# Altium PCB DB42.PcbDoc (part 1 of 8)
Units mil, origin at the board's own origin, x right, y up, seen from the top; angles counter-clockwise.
Board outline 3236.22 x 4456.69 mil, 8 copper layers (Top Layer, MidLayer1, MidLayer2, GND-Layer5, MidLayer3, VCC, MidLayer4, Bottom Layer), stack 62.194 mil thick; 214 components, 470 nets, 1802 pads, 1663 vias.
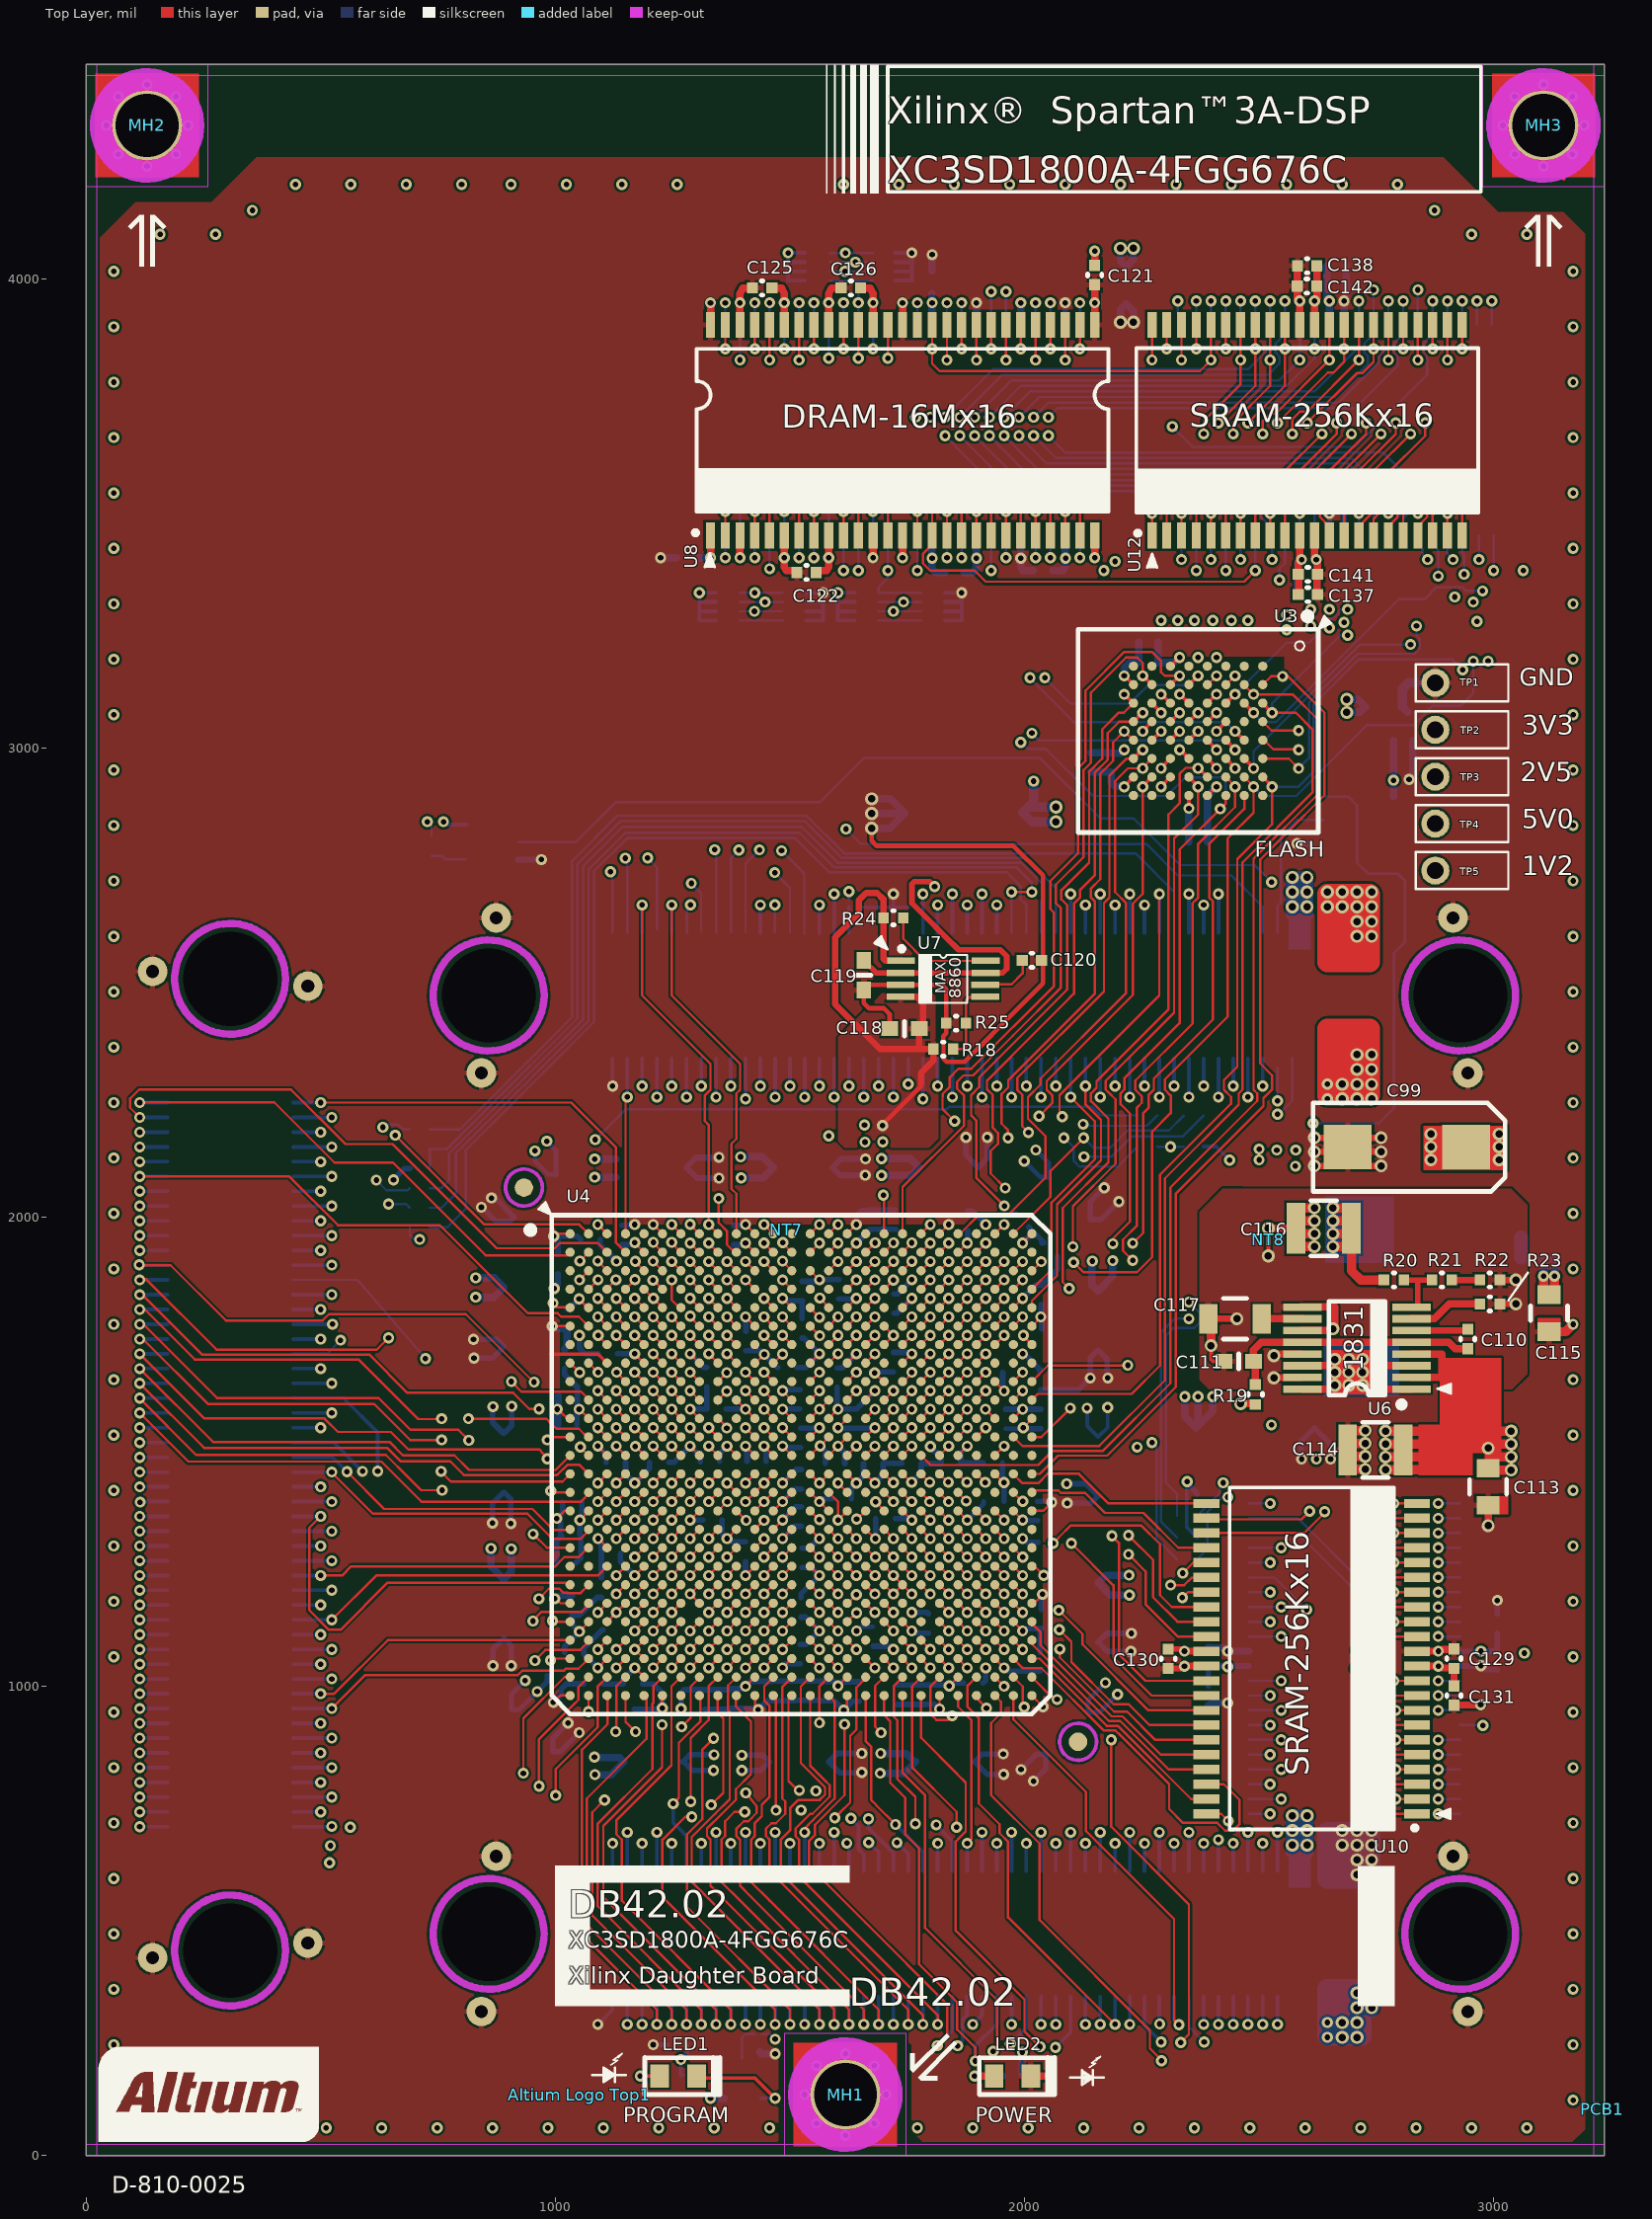
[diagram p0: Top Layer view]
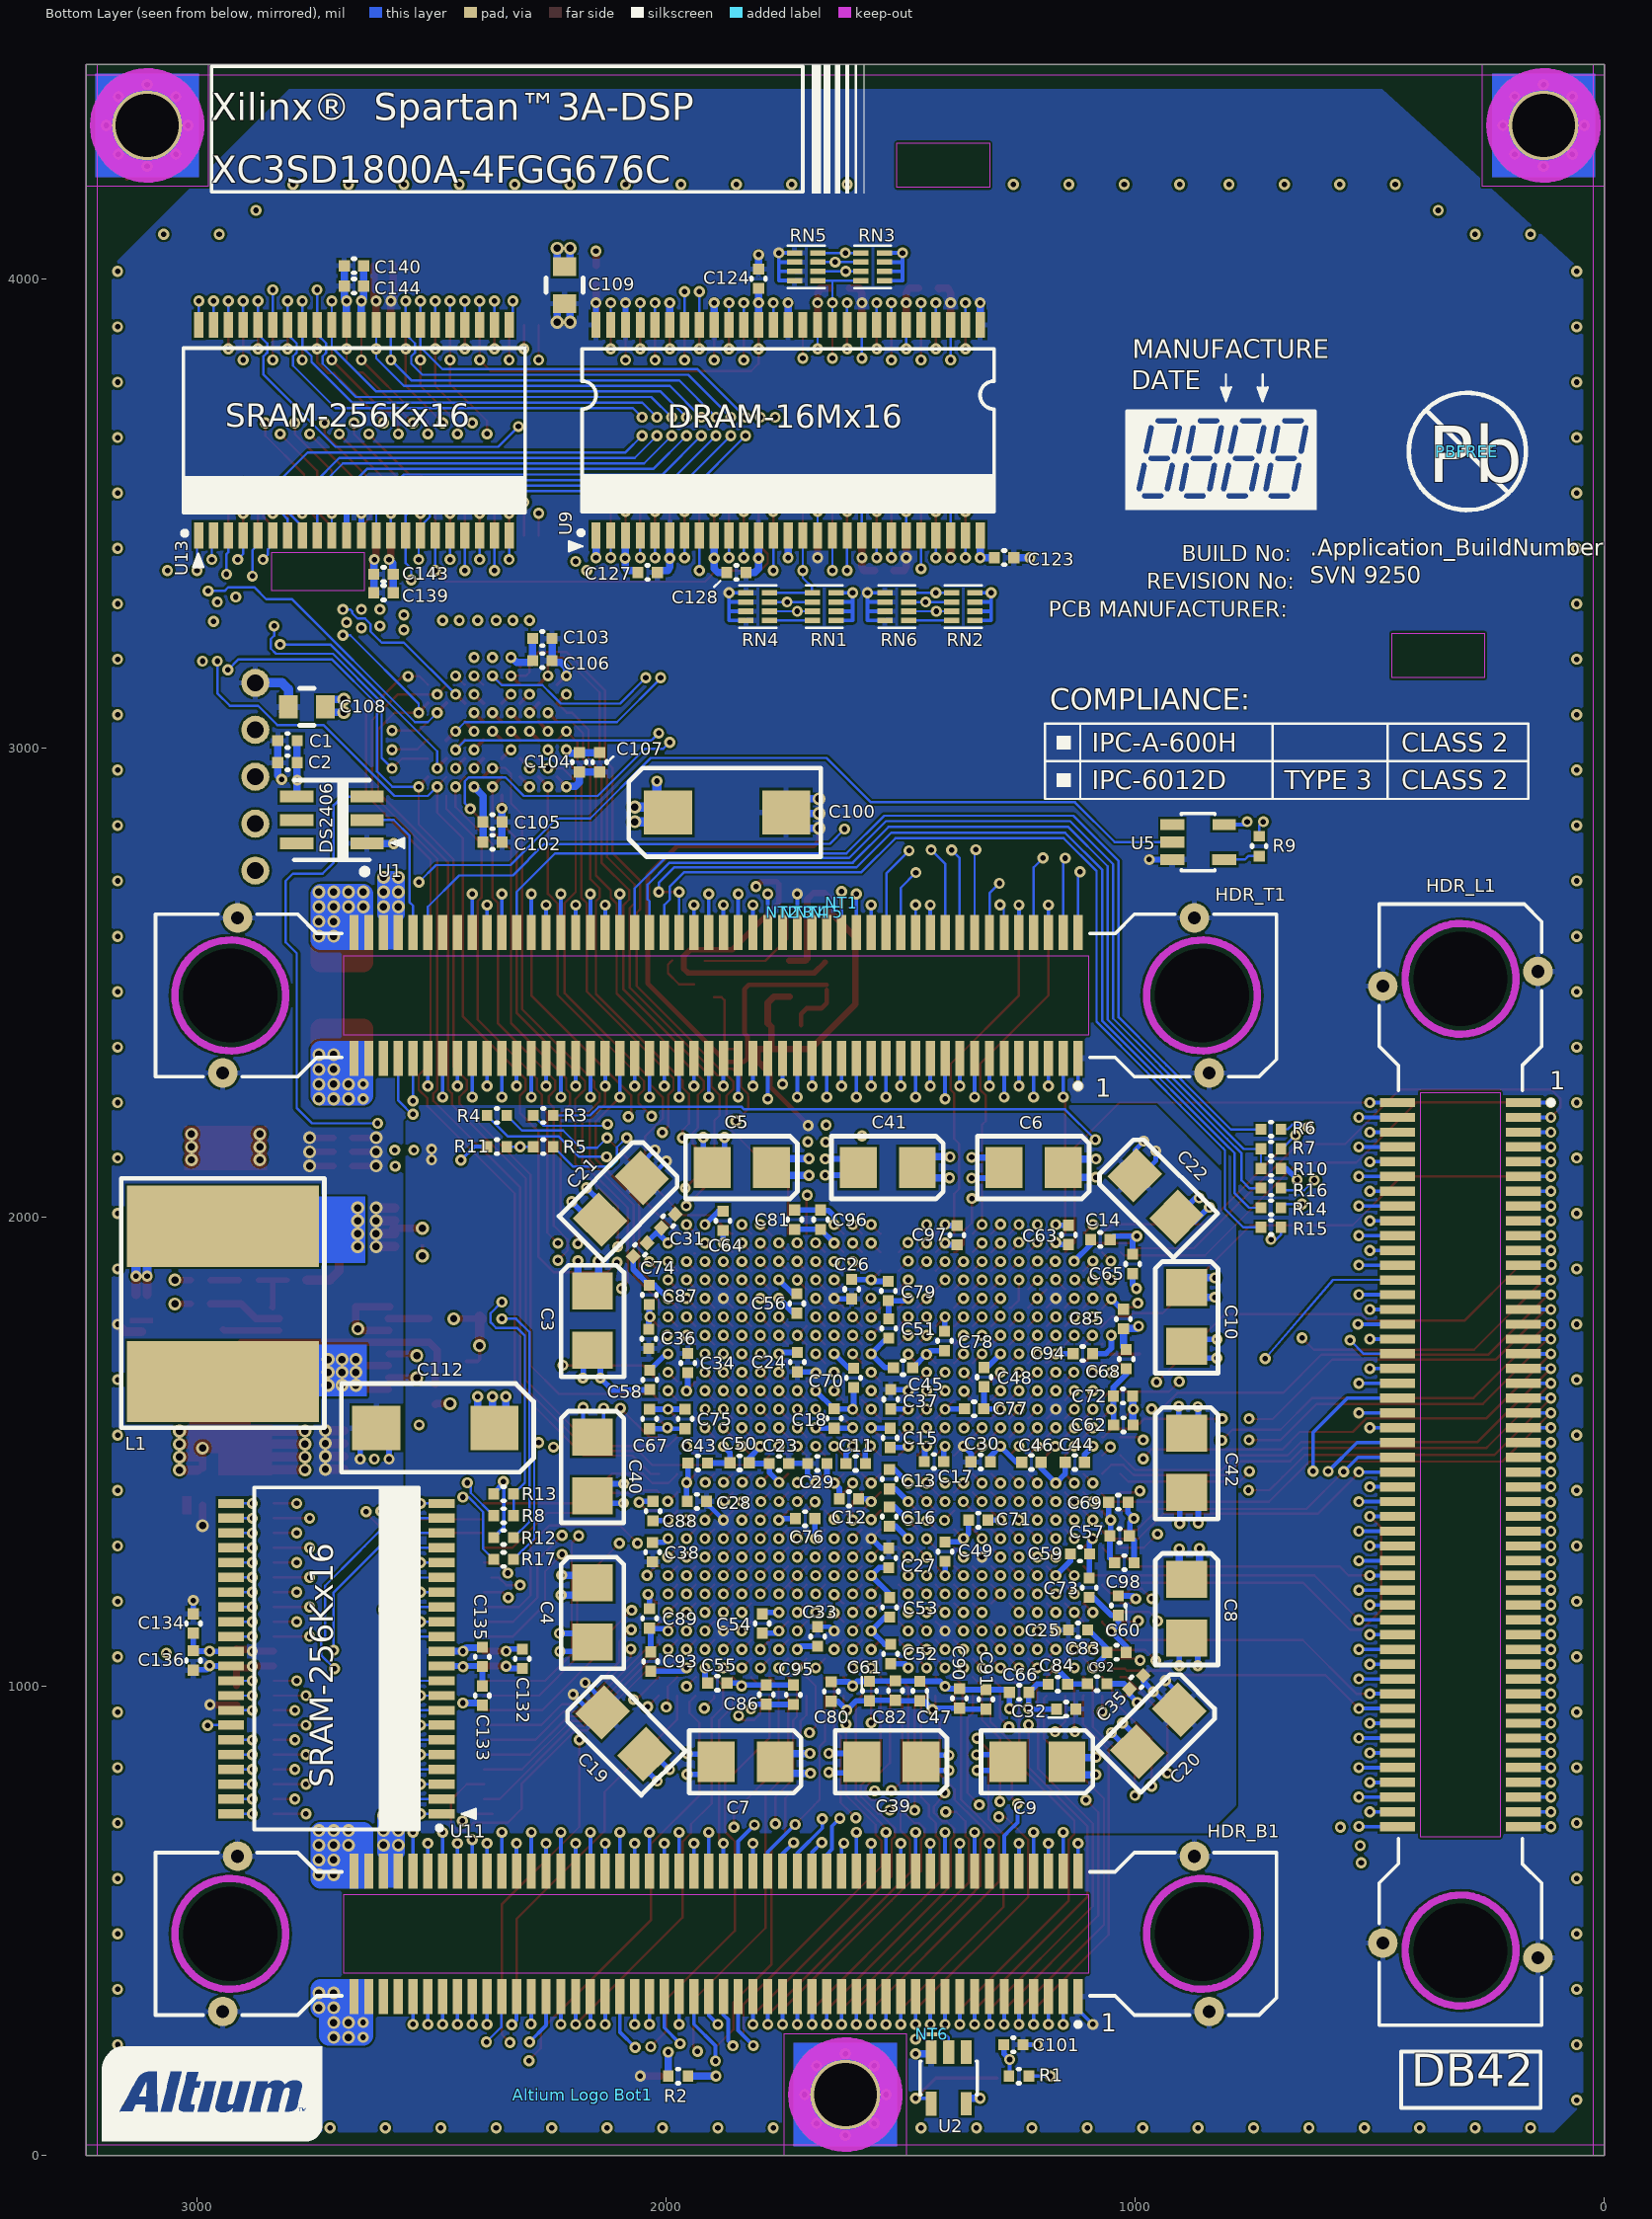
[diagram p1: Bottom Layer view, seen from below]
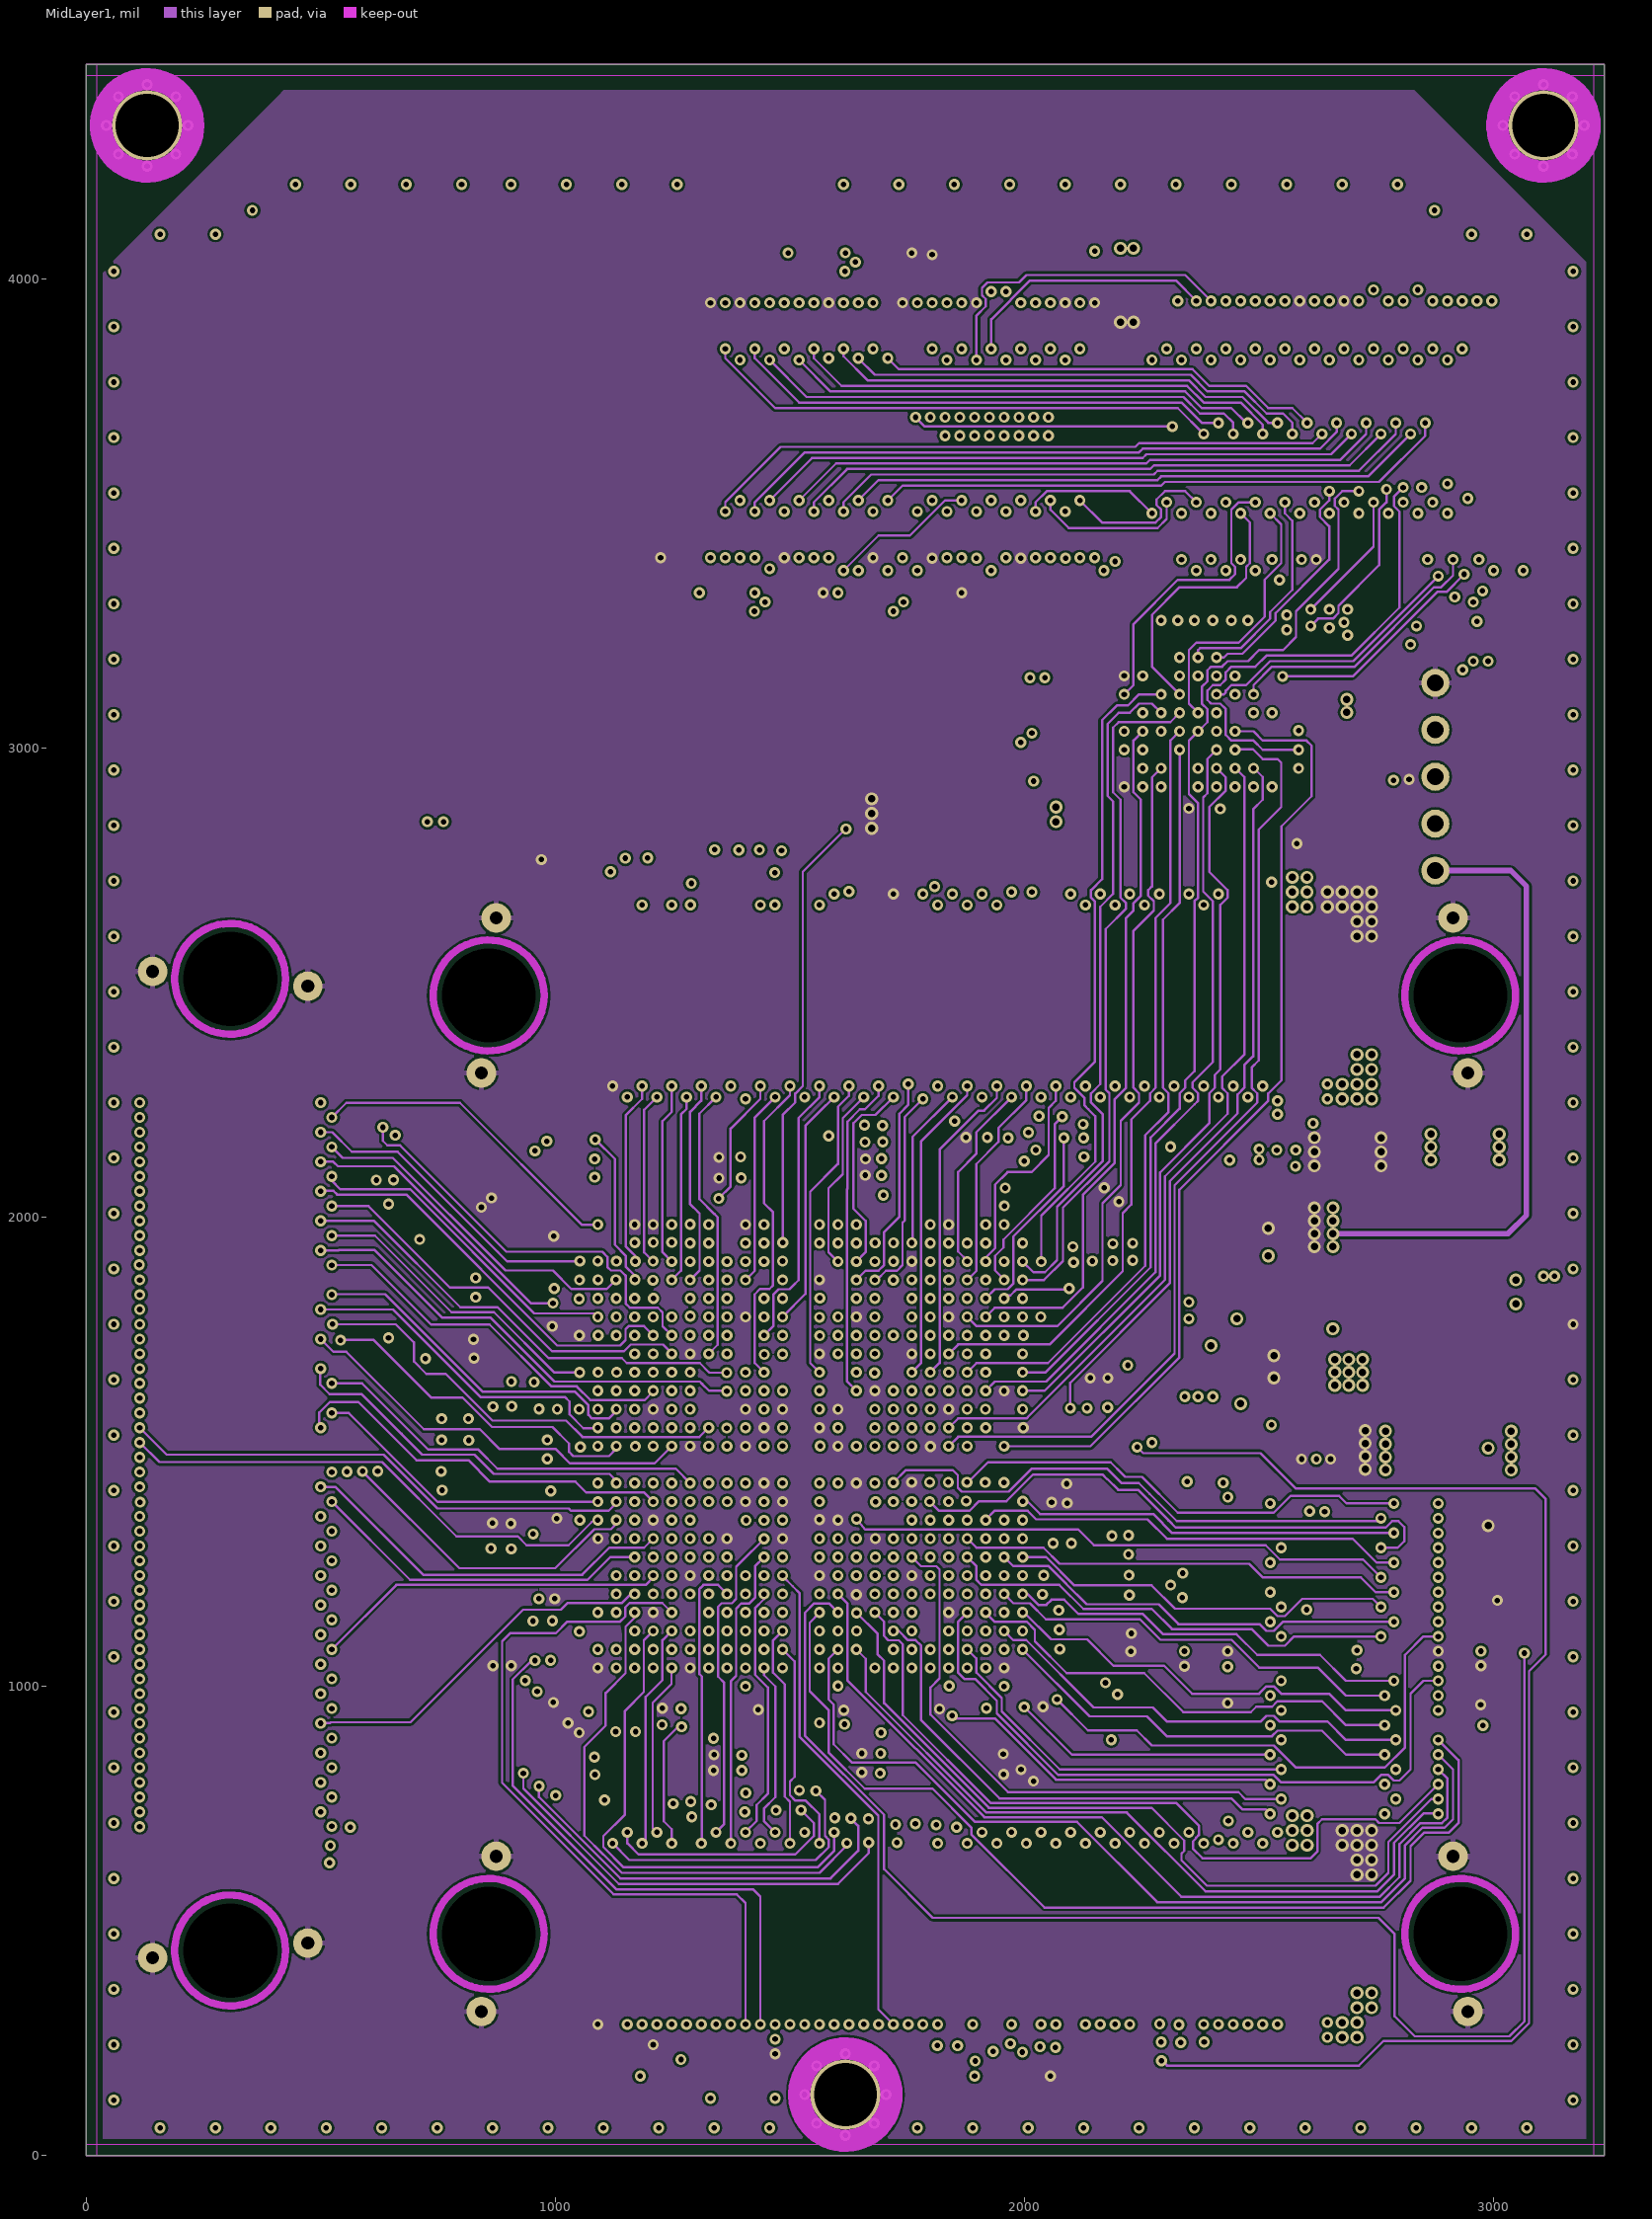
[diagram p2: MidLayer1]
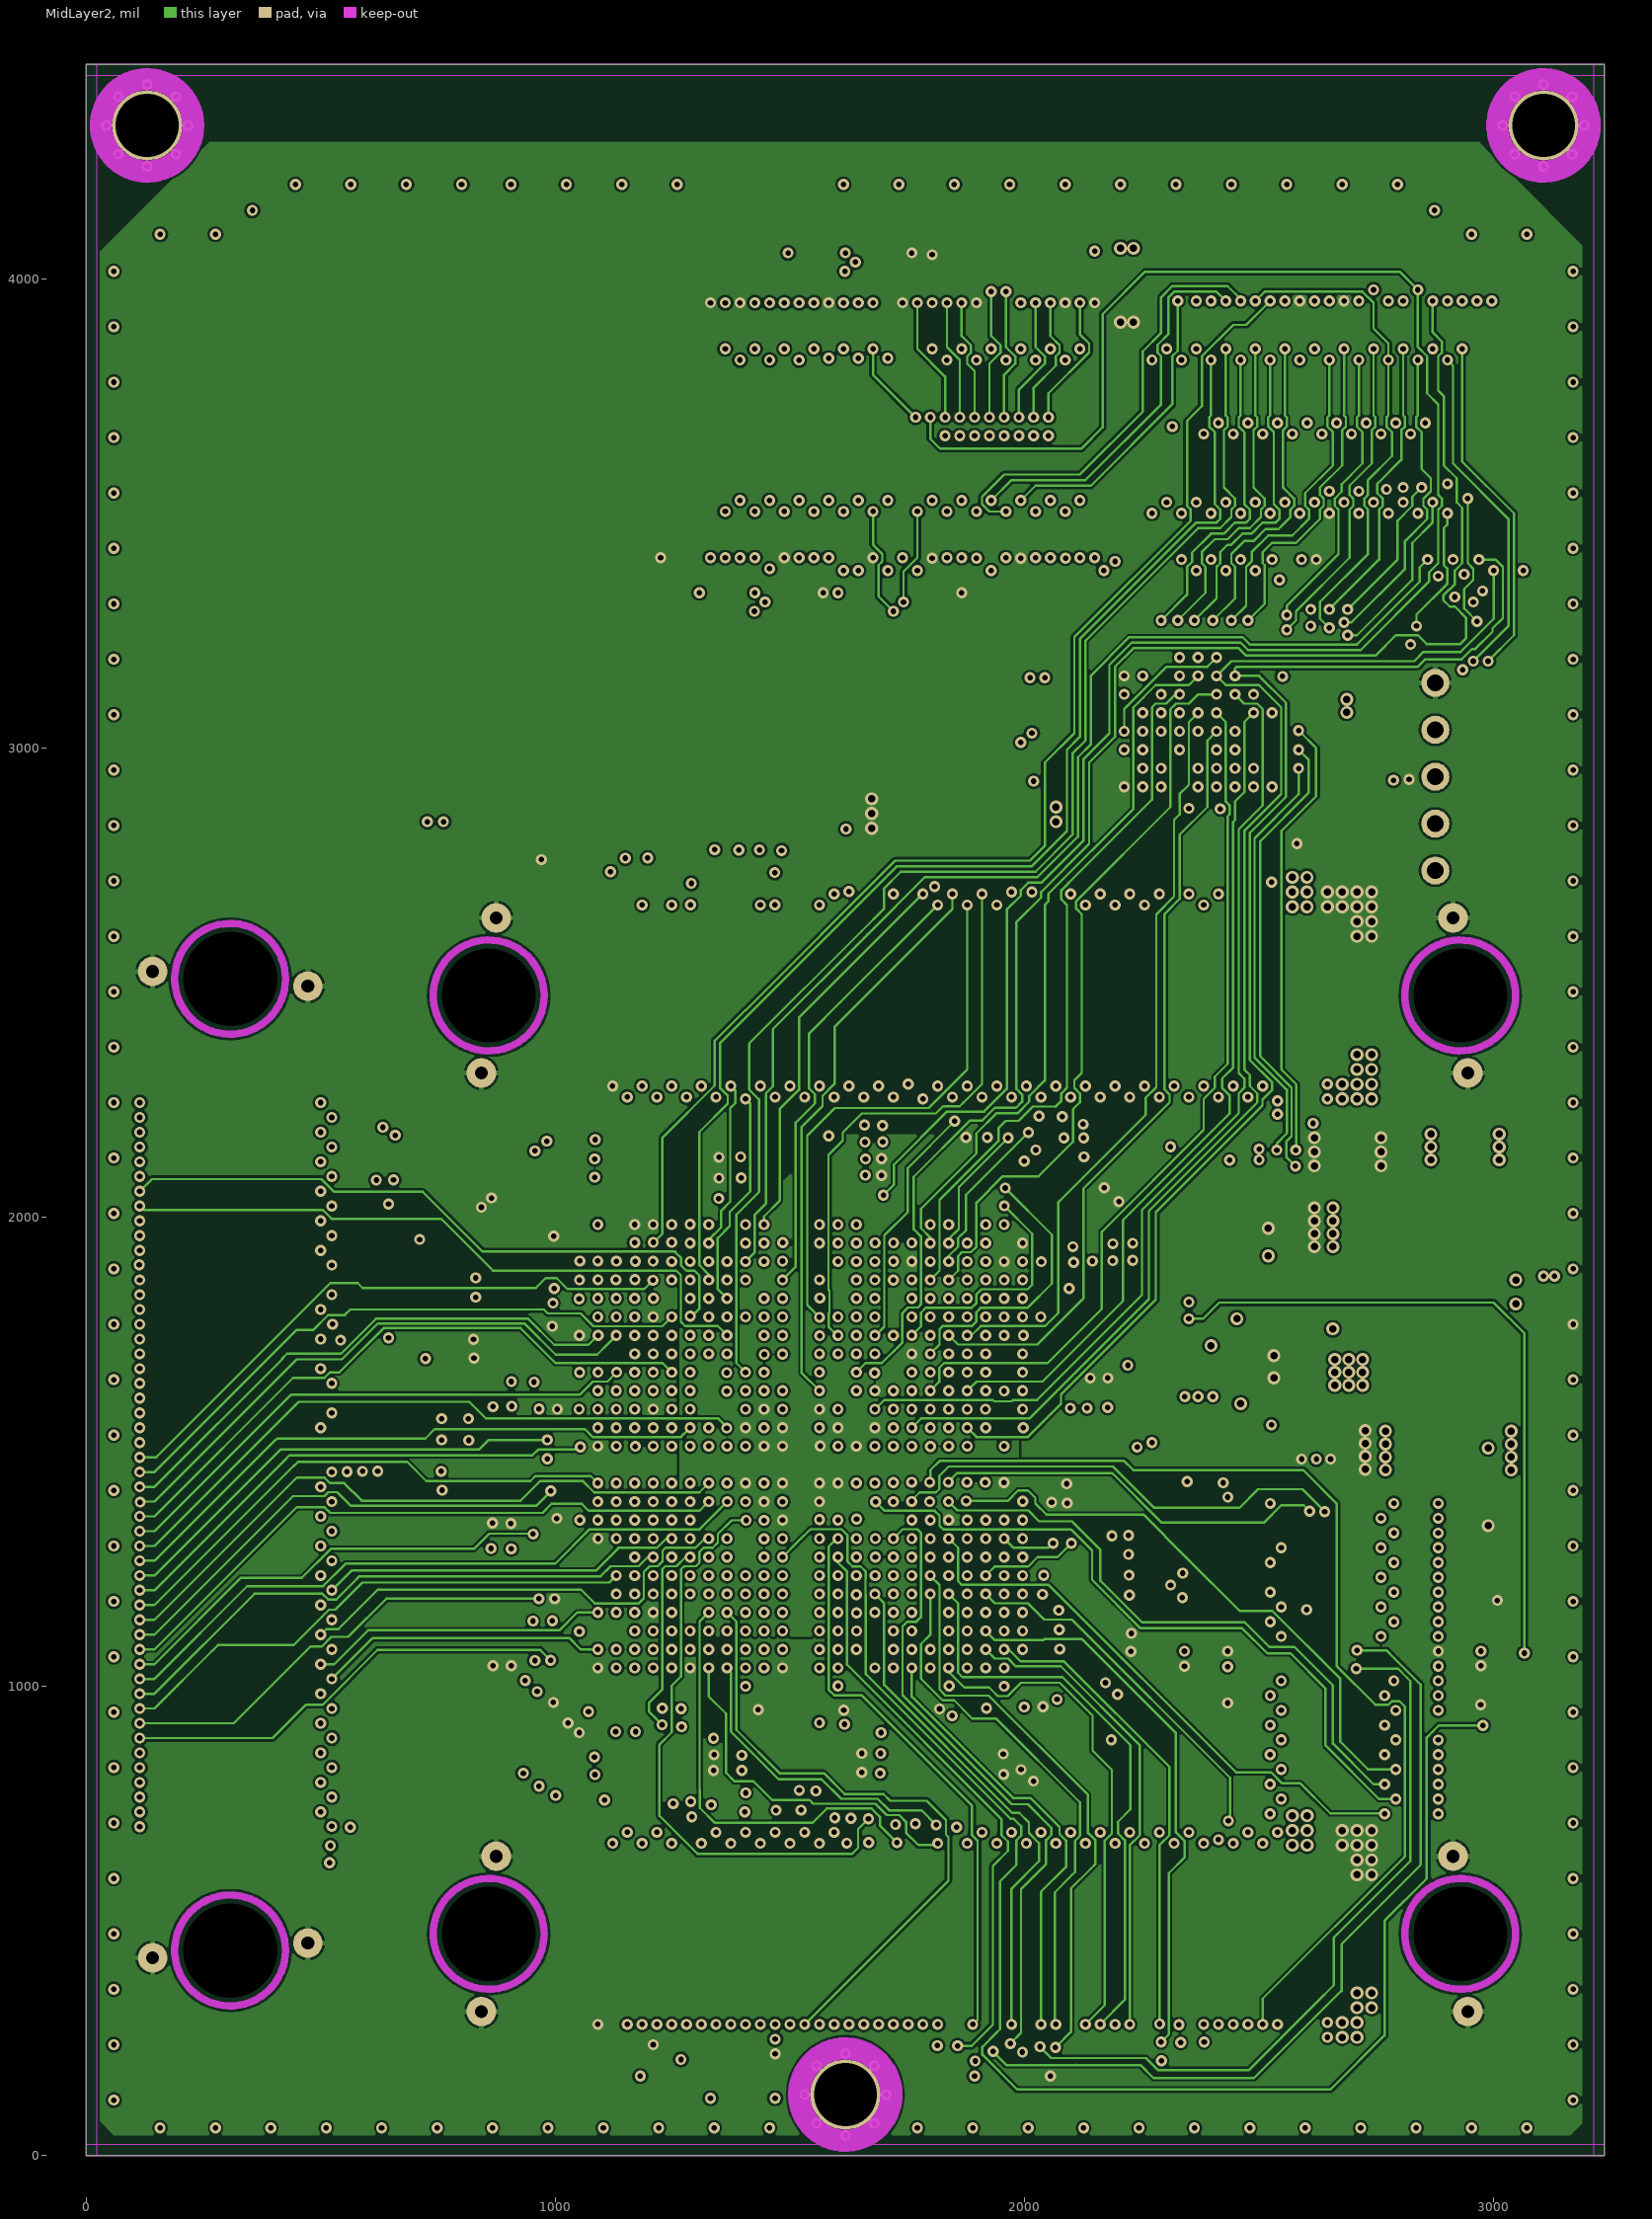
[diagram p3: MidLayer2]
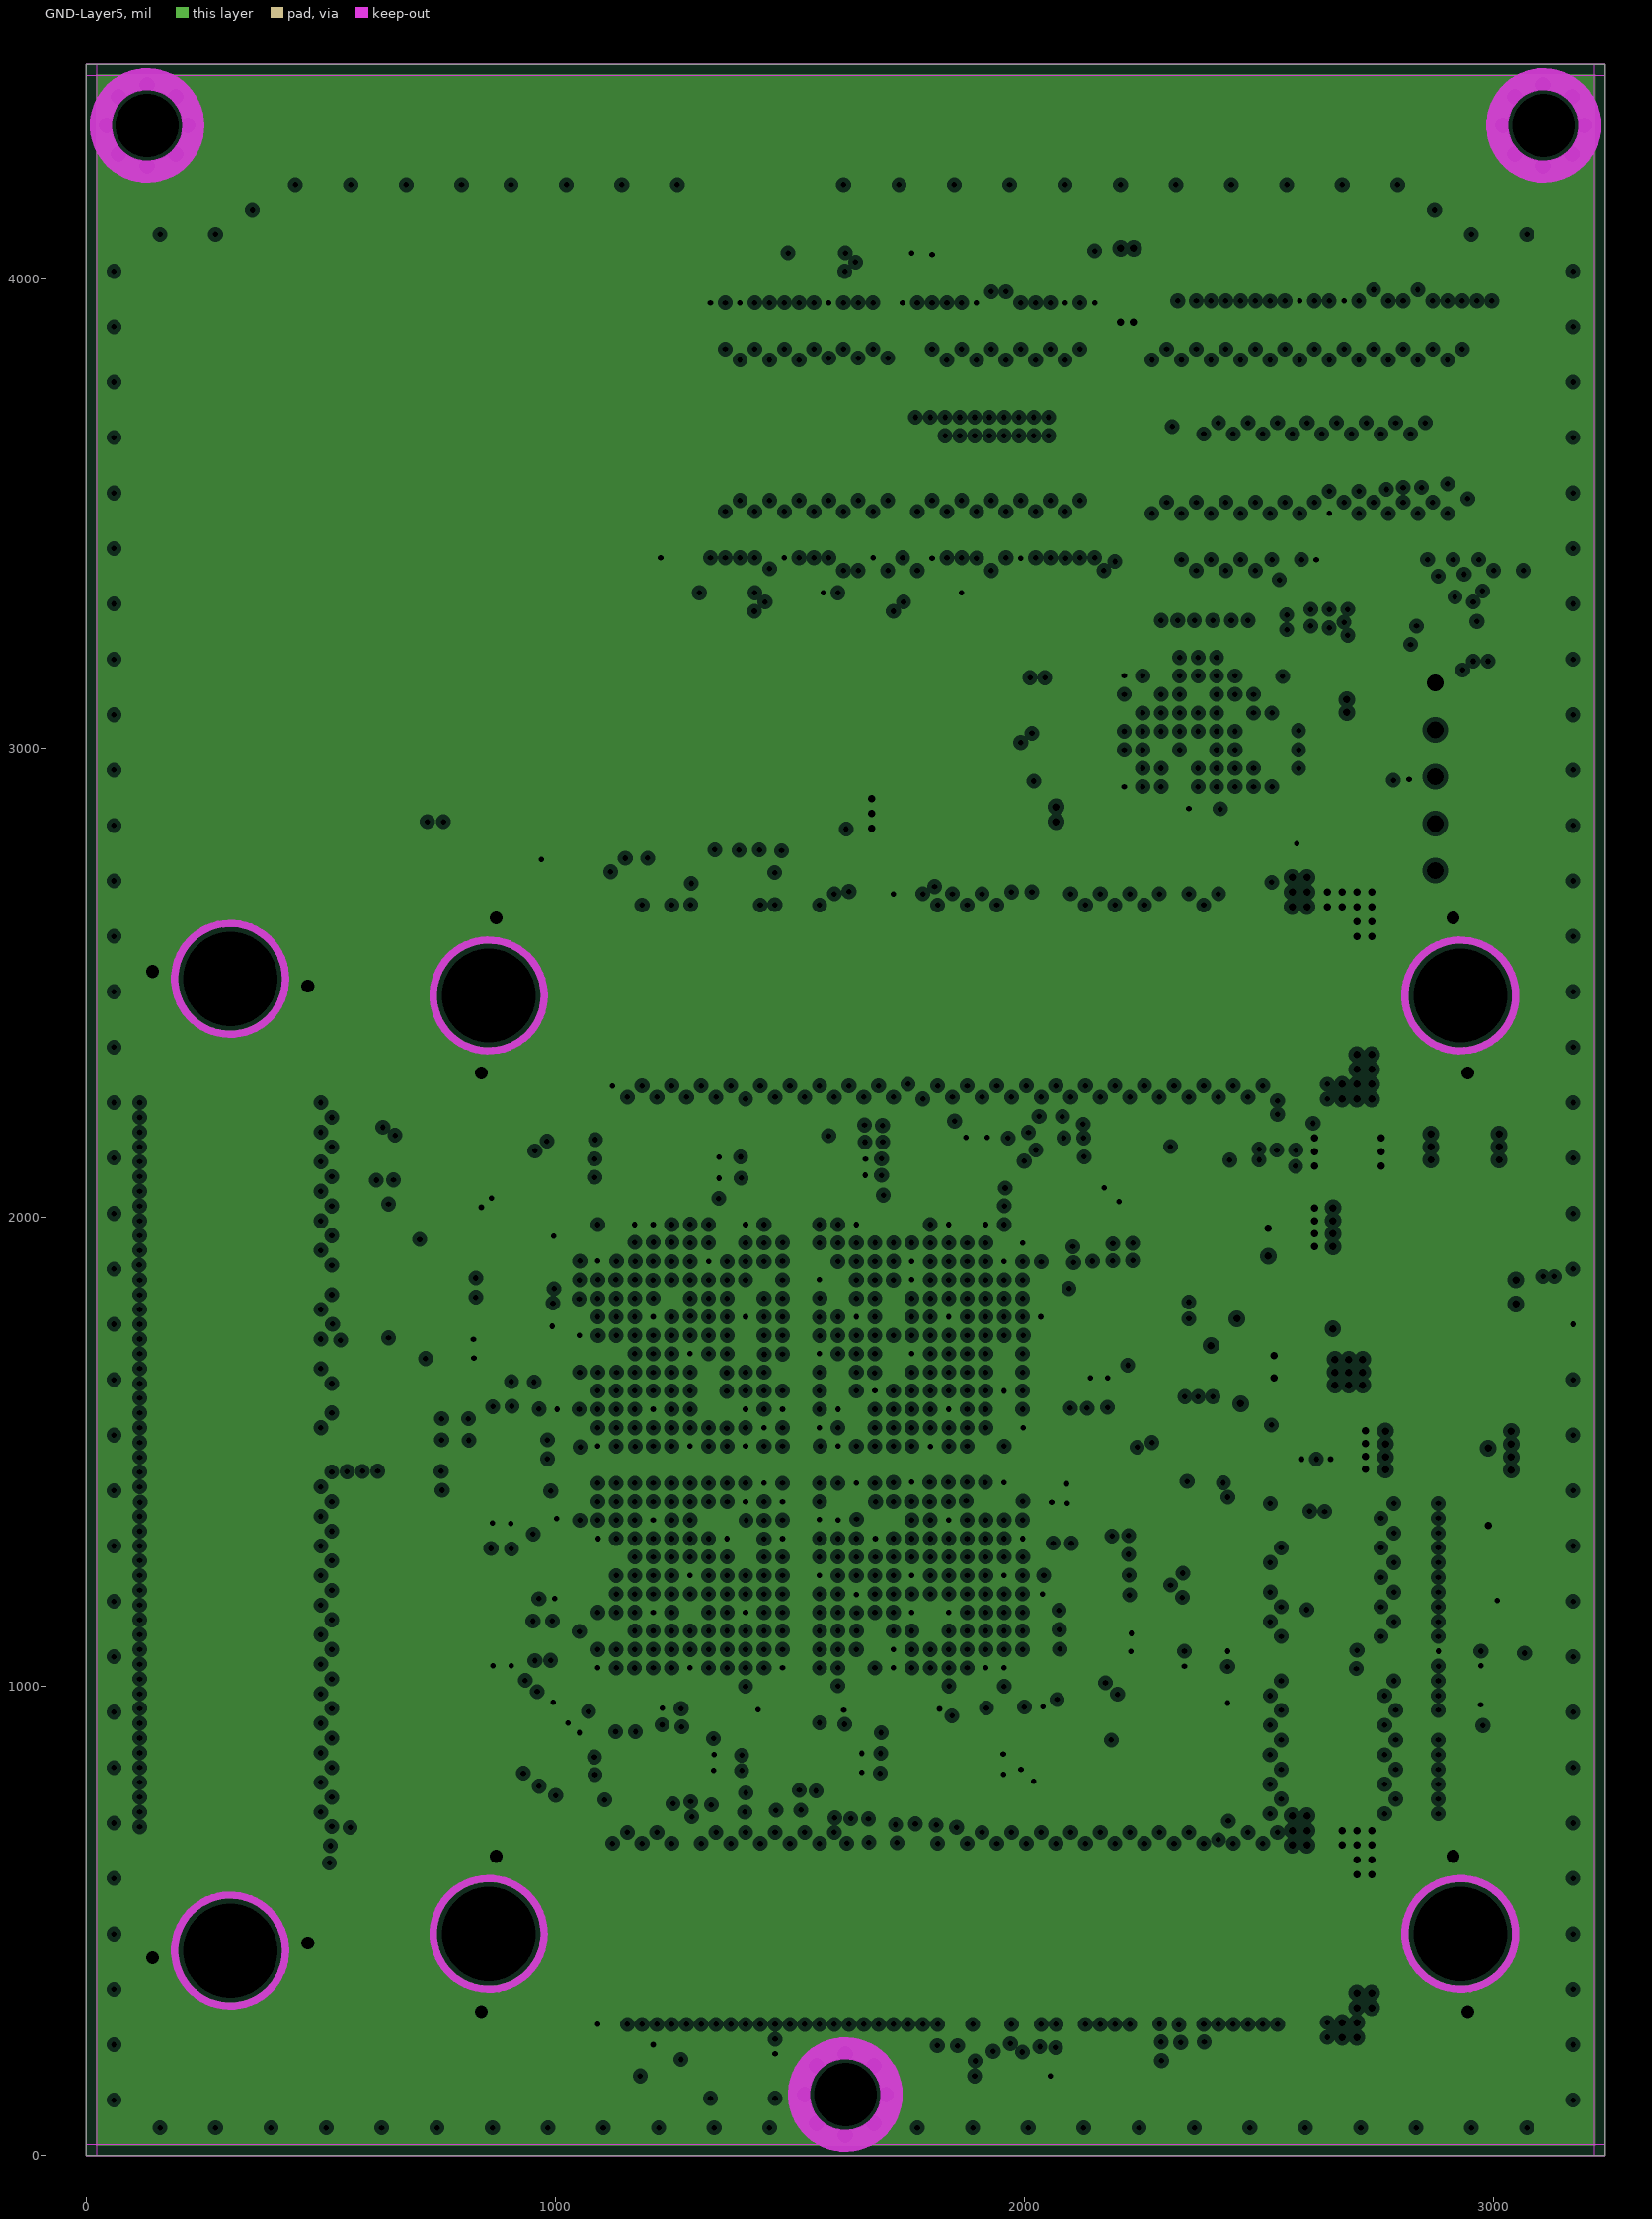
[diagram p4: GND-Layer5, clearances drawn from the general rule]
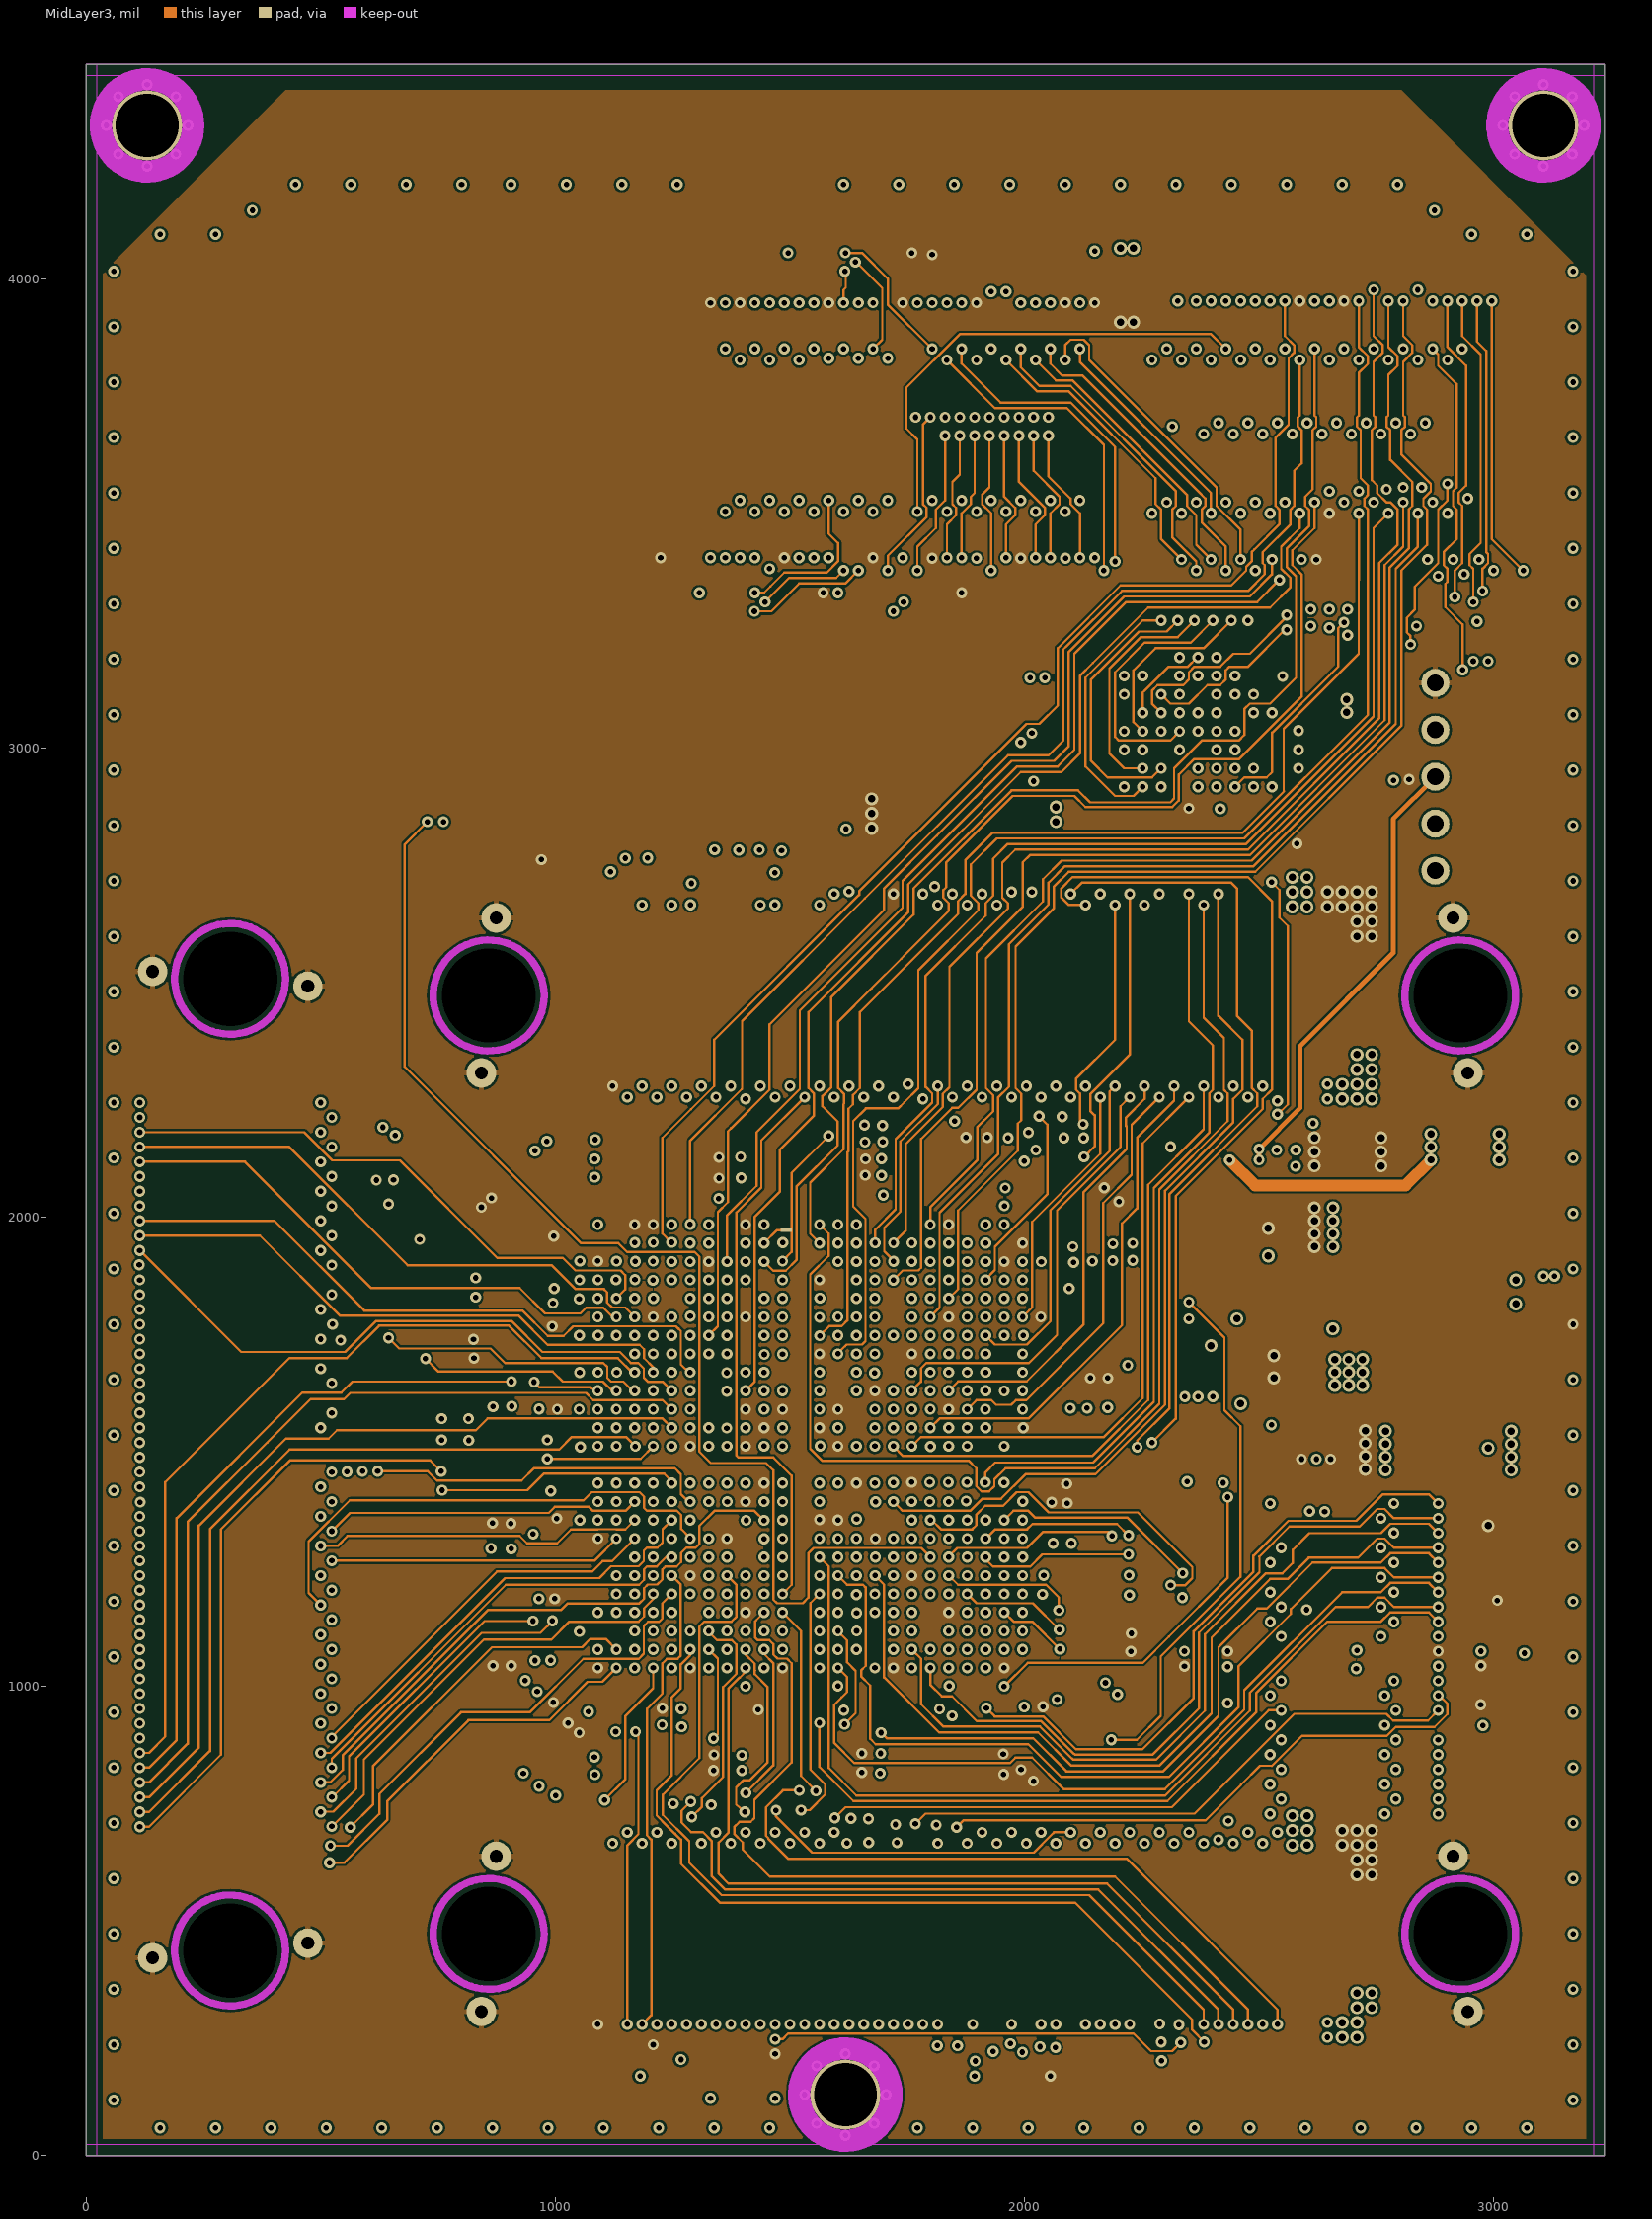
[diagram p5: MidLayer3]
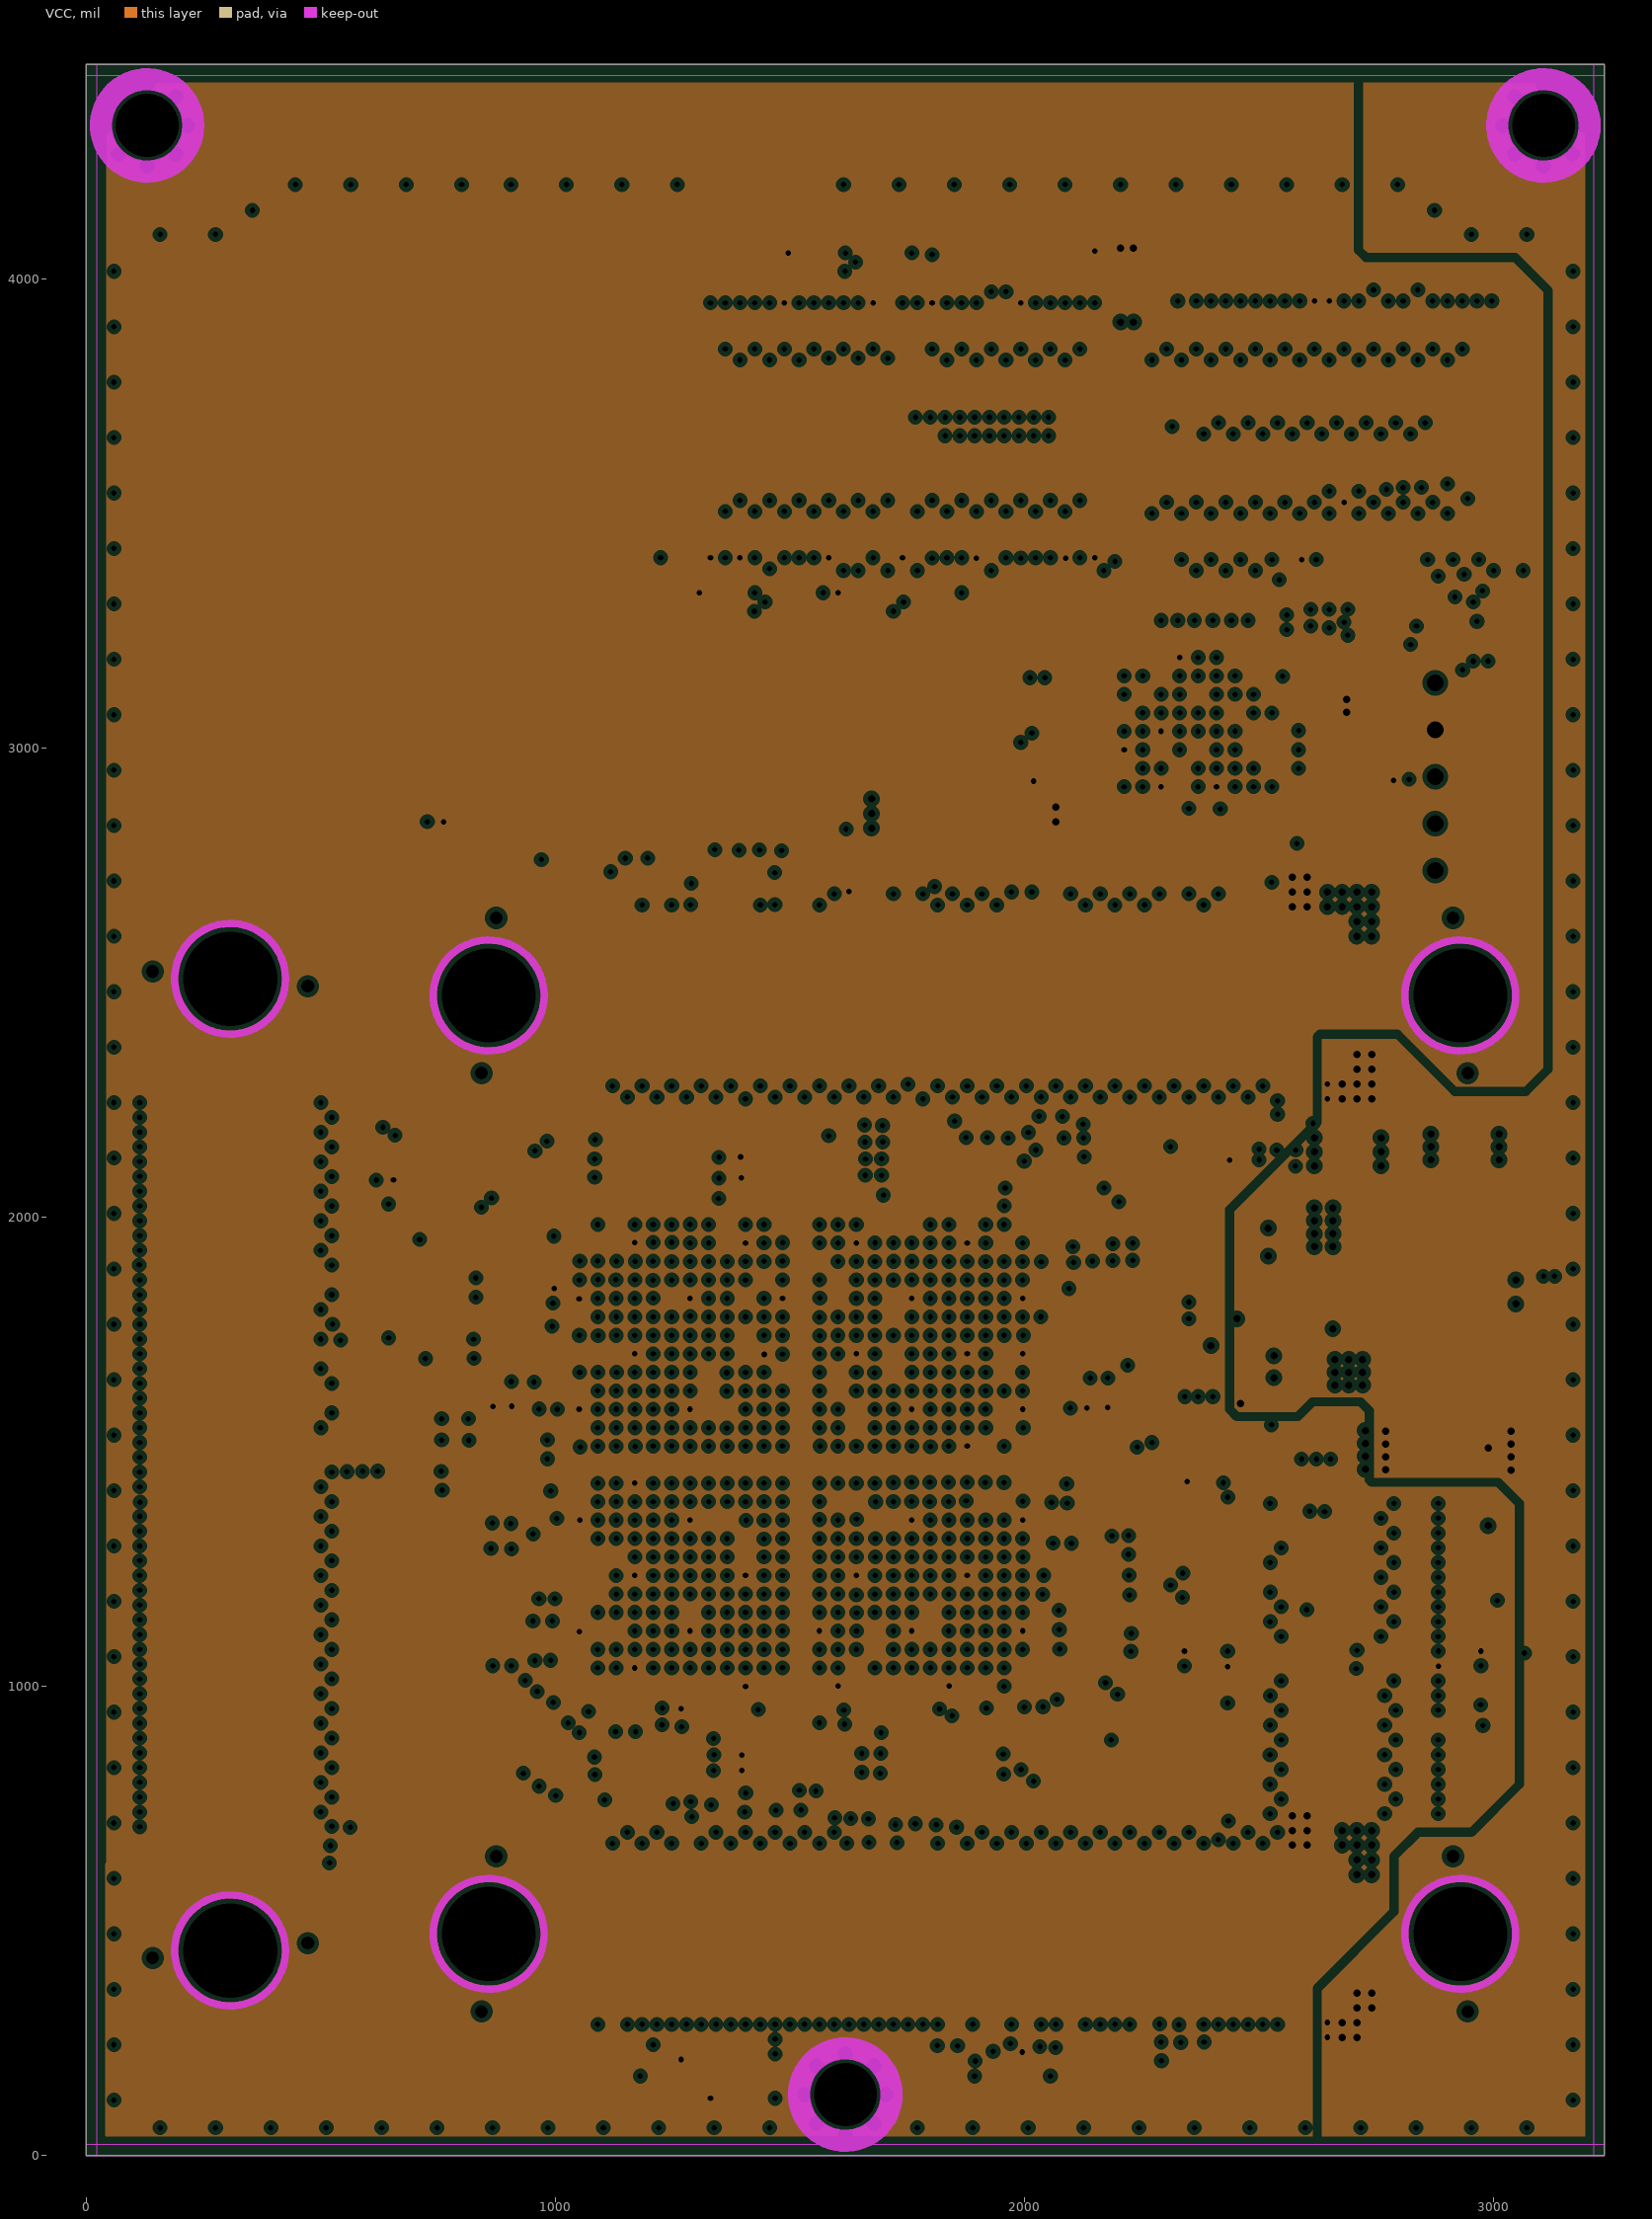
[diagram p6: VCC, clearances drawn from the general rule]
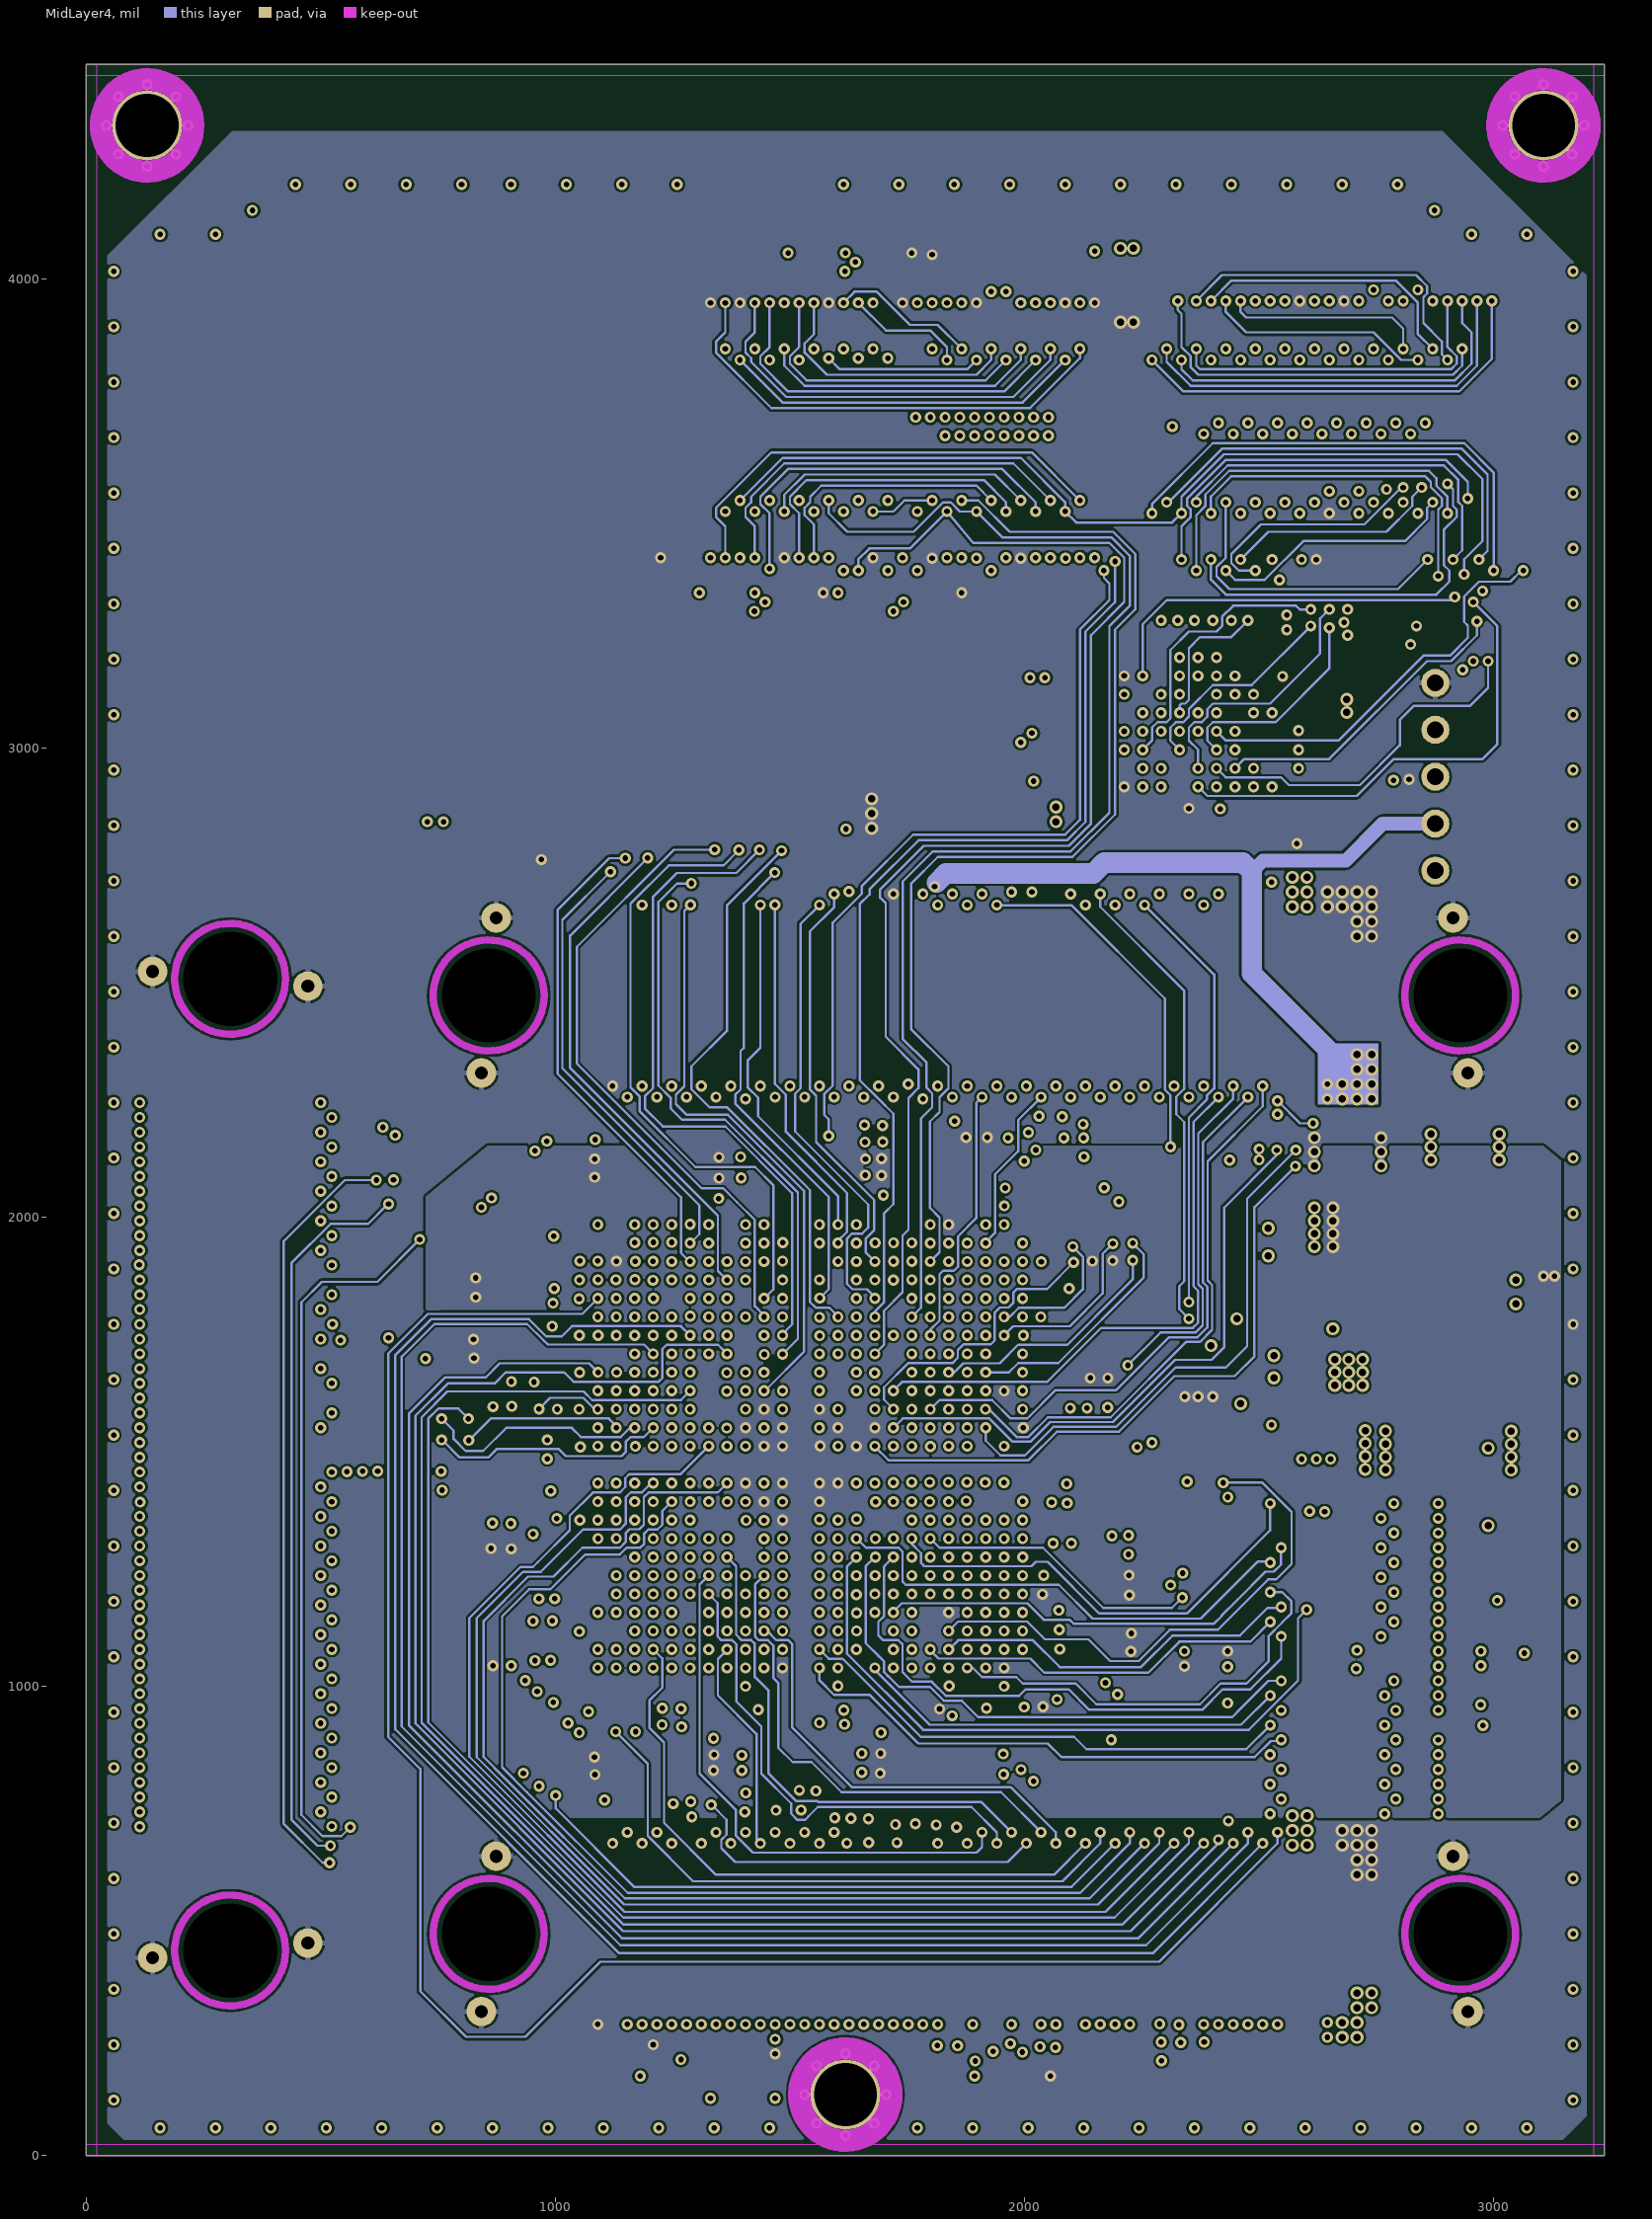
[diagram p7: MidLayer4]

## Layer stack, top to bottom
Top Layer: signal copper 1.7
Dielectric: prepreg 5, FR-4, Dk 4.2
MidLayer1: signal copper 1.4
Dielectric: core 10.3937, FR-4, Dk 4.2
MidLayer2: signal copper 1.4
Dielectric: prepreg 5, FR-4, Dk 4.2
GND-Layer5: plane copper 1.4, net GND
Dielectric: core 10, FR-4, Dk 4.2
MidLayer3: signal copper 1.4
Dielectric: prepreg 5, FR-4, Dk 4.2
VCC: plane copper 1.4, net (Multiple Nets)
Dielectric: core 10, FR-4, Dk 4.2
MidLayer4: signal copper 1.4
Dielectric: prepreg 5, FR-4, Dk 4.2
Bottom Layer: signal copper 1.7

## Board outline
0,0 0,4456.69 1523.62,4456.69 3236.22,4456.69 3236.22,0

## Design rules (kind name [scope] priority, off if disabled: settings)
Clearance "Stencil Clearance" [IsPad and (TouchesRoom('Bypass CAPs')) and Onbottom vs IsPad and (TouchesRoom('Bypass CAPs')) and Onbottom] p1: gap=10
Clearance "Pad-Pad Clearance Same Net" [IsPad vs IsPad] p2: gap=5
Clearance "General Clearance" [All] p3: gap=5
ComponentClearance [(TouchesRoom('Bypass CAPs')) and ((Footprint = 'CAPC1005-STAR') )] p1: gap=10 collisioncheckmode=3 verticalgap=10 showdistances=FALSE
DiffPairsRouting [All] p1: maxlimit=5 minlimit=5 mostfreqgap=5 maxuncoupledlength=200
FabricationTestPointUsage TestPointUsage [All] p1 off: valid=0 allowmultiple=FALSE
FabricationTestpoint Testpoint [All] p1 off: side=3 testpointundercomponent=TRUE minsize=40 maxsize=100 preferedsize=60 minholesize=0 maxholesize=40 preferedholesize=32 testpointgrid=1 allowsidetop=TRUE allowsidebottom=TRUE usegrid=TRUE gridtolerance=0.01
FanoutControl Fanout_BGA [IsBGA] p1: bgadir=Out bgaviamode=Centered fanoutstyle=BGA fanoutdirection=Alternating viagrid=1 // Fanout_BGA (Default Rule)
FanoutControl Fanout_Default [All] p5: bgadir=Out bgaviamode=Centered fanoutstyle=BGA fanoutdirection=Alternating viagrid=1 // Fanout_Default (Default Rule)
HoleSize [All] p1: absolutevalues=TRUE maxlimit=204.72 minlimit=7.87 maxpercent=80.000 minpercent=20.000
HoleToHoleClearance [All] p1: gap=5 allowstackedmicrovias=TRUE
MatchedLengths DiffPair_MatchedLengths [(IsDifferentialPair And (Name = 'DIFF_RX1'))] p1: tolerance=1000 checknetsindiffpair=TRUE checkdiffpairvsdiffpair=TRUE checkothers=TRUE
MinimumAnnularRing MinimumAnnularRing_NonPlated [(ObjectKind = 'Pad') And (HoleDiameter >= '0.7') And (PadIsPlated = 'False')] p1: minimumring=-196.85
MinimumAnnularRing [All] p2: minimumring=5.91
MinimumSolderMaskSliver [All] p1: minsoldermaskwidth=4
PlaneClearance [All] p1: clearance=10
PlaneConnect [All] p1: planeconnectstyle=Direct reliefexpansion=19.68 reliefentries=4 reliefconductorwidth=9.84 reliefairgap=9.84
PolygonConnect PolygonConnect_Via [IsVia] p1: connectstyle=Direct reliefconductorwidth=10 reliefentries=4 polygonreliefangle="90 Angle"
PolygonConnect "PolygonConnect - Heatsink" [(HasFootprint('TO-263') AND InNet('VCCINT'))] p2: connectstyle=Direct reliefconductorwidth=10 reliefentries=4 polygonreliefangle="90 Angle"
PolygonConnect [All] p3: connectstyle=Relief reliefconductorwidth=11.81 reliefentries=4 polygonreliefangle="90 Angle"
RoomDefinition "Bypass CAPS" [InComponentClass('Components Class 1') vs False] p1: confinementstyle=ConfineIn formatcopy=TRUE lockcomponents=FALSE outline 2264.18,2162.83 2264.18,774.41 2260.25,770.47 802.94,770.47 792.12,781.3 792.12,2162.83
RoutingVias [All] p1: holewidth=11.81 width=23.62 viastyle="Through Hole" minholewidth=10.98 minwidth=21.65 maxholewidth=19.68 maxwidth=35.43
ShortCircuit ShortCircuit_1 [Net = 'No Net' vs Net = 'No Net'] p1: allowed=TRUE
ShortCircuit [All] p2: allowed=FALSE
SilkToSilkClearance SilkToSilkClearance_InvToFill [(ObjectKind = 'Text') And (TextKind <> 'Stroke Font') vs (IsFill or IsTrack) and OnSilkScreen] p1: silktosilkclearance=0
SilkToSilkClearance SilkToSilkClearance_Labels [(ObjectKind = 'Text') And (TextKind <> 'Stroke Font') vs (ObjectKind = 'Text') And (TextKind <> 'Stroke Font')] p2: silktosilkclearance=0
SilkToSilkClearance SilkToSilkClearance_Pb [(ObjectKind = 'Text') And (StringText = 'Pb') vs istrack and onsilkscreen] p3: silktosilkclearance=0
SilkToSilkClearance [All] p4: silktosilkclearance=2
SilkscreenOverComponentPads [All] p1: minsilkscreentomaskgap=2
SolderMaskExpansion SolderMaskExpansion_Vias [IsVia] p1: expansion=-25.59
SolderMaskExpansion [All] p2: expansion=1.5
Width [All] p1: maxlimit=98.42 minlimit=5 preferedwidth=5
14 further rules are at their usual default settings.

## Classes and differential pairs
component class DB42_Top: PCB1
component class U_FPGA: NT2 NT3 NT4 NT5 NT6 NT7 R3 R4 R5 R6 R7 R8 R9 R10 R11 R12 R13 R14 R15 R16 R17 U4 U5
component class U_Bypass_3V3: C38_FP C39 C39_FP C40 C40_FP C41 C41_FP C42 C42_FP C43 C43_FP C44 C44_FP C45 C45_FP C46 C46_FP C47 C47_FP C48 C48_FP C49 C49_FP C50 C50_FP C51 C51_FP C52 C52_FP C53 C53_FP C54 C54_FP C55 C55_FP C56 C56_FP C57 C57_FP C58 C58_FP C59 C59_FP C60 C60_FP C61 C61_FP C62 C62_FP C63 C63_FP C64 C64_FP C65 C65_FP C66 C66_FP C67 C67_FP C68 C68_FP C69 C69_FP C70 C70_FP C71 C71_FP C72 C72_FP C73 C73_FP C74 C74_FP C75 C75_FP C76 C76_FP C77 C77_FP C78 C78_FP C79 C79_FP C80 C80_FP C81 C81_FP C82 C82_FP C83 C83_FP C84 C84_FP C85 C85_FP C86 C86_FP C87 C87_FP C88 C88_FP C89 C89_FP C90 C90_FP C91 C91_FP C92 C92_FP C93 C93_FP C94 C94_FP C95 C95_FP C96 C96_FP C97 C97_FP C98 C98_FP C99_FP C100_FP C101_FP C102_FP C103_FP C104_FP C105_FP C106_FP
component class U_Bypass_2V5: C3_MB C19 C20 C21 C21_FP C22 C22_FP C23 C23_FP C24 C24_FP C25 C25_FP C26 C26_FP C27 C27_FP C28 C28_FP C29 C29_FP C30 C30_FP C31 C31_FP C32 C32_FP C33 C33_FP C34 C34_FP C35 C35_FP C36 C36_FP C37 C37_FP C38 C108_FP C109_FP
component class U_Bypass_1V2: C1_FP C2_FP C3 C3_FP C4 C4_FP C5 C5_FP C6 C6_FP C7 C7_FP C8 C8_FP C9 C9_FP C10 C10_FP C11 C11_FP C12 C12_FP C13 C13_FP C14 C14_FP C15 C15_FP C16 C16_FP C17 C17_FP C18 C18_FP C19_FP
channel class SRAM_256Kx16_TSOP44: U_SRAM_K6R4016V1D-TC10T_256Kx161 U_SRAM_K6R4016V1D-TC10T_256Kx162
component class COM_SRAM: C137 C138 C139 C140 C141 C142 C143 C144 U12 U13
component class COM_SDRAM: C121 C122 C123 C124 C125 C126 C127 C128 U8 U9
component class U_MOUNTS: "Altium Logo Bot1" "Altium Logo Top1" LB1 MH1 MH2 MH3
component class U_CommonMemory_Termination: RN1 RN2 RN3 RN4 RN5 RN6 RN7 RN8 RN9 RN10 RN11 RN12 RN13 RN14 RN15 RN16 RN17 RN18 RN19 RN20 RN21 RN22 RN23 RN24 RN25 RN26 RN27 RN28 RN29 RN30 RN31 RN32 RN35 RN36
component class COM_FLASH: C102 C103 C104 C105 C106 C107 U3
net class PWRNET: 1V2 2V5 3V3 5V0 AGND GND
differential pair class DIFF_OUT: DIFF_TX0 DIFF_TX1 DIFF_TX2 DIFF_TX3
differential pair class DIFF_IN: DIFF_RX0 DIFF_RX1 DIFF_RX2 DIFF_RX3
net class SW[4..0]: SW0 SW1 SW2 SW3 SW4
net class LED[7..0]: LED0 LED1 LED2 LED3 LED4 LED5 LED6 LED7
net class IO[35..0]: IO0 IO1 IO2 IO3 IO4 IO5 IO6 IO7 IO8 IO9 IO10 IO11 IO12 IO13 IO14 IO15 IO16 IO17 IO18 IO19 IO20 IO21 IO22 IO23 IO24 IO25 IO26 IO27 IO28 IO29 IO30 IO31 IO32 IO33 IO34 IO35
net class FPGA_M[2..0]: FPGA_M0 FPGA_M1 FPGA_M2
net class FPGA_ID[3..0]: FPGA_ID0 FPGA_ID1 FPGA_ID2 FPGA_ID3
net class DIP[7..0]: DIP0 DIP1 DIP2 DIP3 DIP4 DIP5 DIP6 DIP7
net class BUS_NBE[3..0]: BUS_NBE0 BUS_NBE1 BUS_NBE2 BUS_NBE3
net class BUS_D[31..0]: BUS_D0 BUS_D1 BUS_D2 BUS_D3 BUS_D4 BUS_D5 BUS_D6 BUS_D7 BUS_D8 BUS_D9 BUS_D10 BUS_D11 BUS_D12 BUS_D13 BUS_D14 BUS_D15 BUS_D16 BUS_D17 BUS_D18 BUS_D19 BUS_D20 BUS_D21 BUS_D22 BUS_D23 BUS_D24 BUS_D25 BUS_D26 BUS_D27 BUS_D28 BUS_D29 BUS_D30 BUS_D31
component class U_MotherBoardConnectors: HDR_B1 HDR_L HDR_L1 HDR_T1 NT1
net class CLKS: BUS_SDRAM_CLK IO18 IO19 NEXUS_TCK
net class BUS_A[24..1]: BUS_A1 BUS_A2 BUS_A3 BUS_A4 BUS_A5 BUS_A6 BUS_A7 BUS_A8 BUS_A9 BUS_A10 BUS_A11 BUS_A12 BUS_A13 BUS_A14 BUS_A15 BUS_A16 BUS_A17 BUS_A18 BUS_A19 BUS_A20 BUS_A21 BUS_A22 BUS_A23 BUS_A24
net class DAU_TFT_BLUE[4..0]: DAU_TFT_BLUE0 DAU_TFT_BLUE1 DAU_TFT_BLUE2 DAU_TFT_BLUE3 DAU_TFT_BLUE4
net class DAU_TFT_CL[3..1]: DAU_TFT_CL1 DAU_TFT_CL2 DAU_TFT_CL3
net class DAU_TFT_GREEN[5..0]: DAU_TFT_GREEN0 DAU_TFT_GREEN1 DAU_TFT_GREEN2 DAU_TFT_GREEN3 DAU_TFT_GREEN4 DAU_TFT_GREEN5
net class DAU_TFT_RED[4..0]: DAU_TFT_RED0 DAU_TFT_RED1 DAU_TFT_RED2 DAU_TFT_RED3 DAU_TFT_RED4
net class EXTEND_A[49..0]: EXTEND_A0 EXTEND_A1 EXTEND_A2 EXTEND_A3 EXTEND_A4 EXTEND_A5 EXTEND_A6 EXTEND_A7 EXTEND_A8 EXTEND_A9 EXTEND_A10 EXTEND_A11 EXTEND_A12 EXTEND_A13 EXTEND_A14 EXTEND_A15 EXTEND_A16 EXTEND_A17 EXTEND_A18 EXTEND_A19 EXTEND_A20 EXTEND_A21 EXTEND_A22 EXTEND_A23 EXTEND_A24 EXTEND_A25 EXTEND_A26 EXTEND_A27 EXTEND_A28 EXTEND_A29 EXTEND_A30 EXTEND_A31 EXTEND_A32 EXTEND_A33 EXTEND_A34 EXTEND_A35 EXTEND_A36 EXTEND_A37 EXTEND_A38 EXTEND_A39 EXTEND_A40 EXTEND_A41 EXTEND_A42 EXTEND_A43 EXTEND_A44 EXTEND_A45 EXTEND_A46 EXTEND_A47 EXTEND_A48 EXTEND_A49
net class EXTEND_B[49..0]: EXTEND_B0 EXTEND_B1 EXTEND_B2 EXTEND_B3 EXTEND_B4 EXTEND_B5 EXTEND_B6 EXTEND_B7 EXTEND_B8 EXTEND_B9 EXTEND_B10 EXTEND_B11 EXTEND_B12 EXTEND_B13 EXTEND_B14 EXTEND_B15 EXTEND_B16 EXTEND_B17 EXTEND_B18 EXTEND_B19 EXTEND_B20 EXTEND_B21 EXTEND_B22 EXTEND_B23 EXTEND_B24 EXTEND_B25 EXTEND_B26 EXTEND_B27 EXTEND_B28 EXTEND_B29 EXTEND_B30 EXTEND_B31 EXTEND_B32 EXTEND_B33 EXTEND_B34 EXTEND_B35 EXTEND_B36 EXTEND_B37 EXTEND_B38 EXTEND_B39 EXTEND_B40 EXTEND_B41 EXTEND_B42 EXTEND_B43 EXTEND_B44 EXTEND_B45 EXTEND_B46 EXTEND_B47 EXTEND_B48 EXTEND_B49
net class EXTEND_C[49..0]: EXTEND_C0 EXTEND_C1 EXTEND_C2 EXTEND_C3 EXTEND_C4 EXTEND_C5 EXTEND_C6 EXTEND_C7 EXTEND_C8 EXTEND_C9 EXTEND_C10 EXTEND_C11 EXTEND_C12 EXTEND_C13 EXTEND_C14 EXTEND_C15 EXTEND_C16 EXTEND_C17 EXTEND_C18 EXTEND_C19 EXTEND_C20 EXTEND_C21 EXTEND_C22 EXTEND_C23 EXTEND_C24 EXTEND_C25 EXTEND_C26 EXTEND_C27 EXTEND_C28 EXTEND_C29 EXTEND_C30 EXTEND_C31 EXTEND_C32 EXTEND_C33 EXTEND_C34 EXTEND_C35 EXTEND_C36 EXTEND_C37 EXTEND_C38 EXTEND_C39 EXTEND_C40 EXTEND_C41 EXTEND_C42 EXTEND_C43 EXTEND_C44 EXTEND_C45 EXTEND_C46 EXTEND_C47 EXTEND_C48 EXTEND_C49
component class U_PSU: C108 C109 NT8 R18 TP1 TP2 TP3 TP4 TP5
net class SRAM1_A[18..0]: SRAM1_A0 SRAM1_A1 SRAM1_A2 SRAM1_A3 SRAM1_A4 SRAM1_A5 SRAM1_A6 SRAM1_A7 SRAM1_A8 SRAM1_A9 SRAM1_A10 SRAM1_A11 SRAM1_A12 SRAM1_A13 SRAM1_A14 SRAM1_A15 SRAM1_A16 SRAM1_A17 SRAM1_A18
net class SRAM1_D[15..0]: SRAM1_D0 SRAM1_D1 SRAM1_D2 SRAM1_D3 SRAM1_D4 SRAM1_D5 SRAM1_D6 SRAM1_D7 SRAM1_D8 SRAM1_D9 SRAM1_D10 SRAM1_D11 SRAM1_D12 SRAM1_D13 SRAM1_D14 SRAM1_D15
net class SRAM2_A[18..0]: SRAM2_A0 SRAM2_A1 SRAM2_A2 SRAM2_A3 SRAM2_A4 SRAM2_A5 SRAM2_A6 SRAM2_A7 SRAM2_A8 SRAM2_A9 SRAM2_A10 SRAM2_A11 SRAM2_A12 SRAM2_A13 SRAM2_A14 SRAM2_A15 SRAM2_A16 SRAM2_A17 SRAM2_A18
net class SRAM2_D[15..0]: SRAM2_D0 SRAM2_D1 SRAM2_D2 SRAM2_D3 SRAM2_D4 SRAM2_D5 SRAM2_D6 SRAM2_D7 SRAM2_D8 SRAM2_D9 SRAM2_D10 SRAM2_D11 SRAM2_D12 SRAM2_D13 SRAM2_D14 SRAM2_D15
component class U_1WB_DS2406_EPROM: C1 C2 U1
component class U_DaughterBoard_LEDS: C101 LED1 LED2 R1 R2 U2
component class U_SRAM_K6R4016V1D-TC10T_256Kx161: C129 C130 C131 C132 U10
component class U_SRAM_K6R4016V1D-TC10T_256Kx162: C1_SM C2_SM C4_SM C133 C134 C135 C136 U1_SM U11
component class U_PSU_MAX1831_1V2_ALT: C110 C111 C112 C113 C114 C115 C116 C117 L1 R19 R20 R21 R22 R23 TP7 TP8 U6
component class U_PSU_MAX8860_ADJ: C118 C119 C120 R24 R25 U7
component class U_Bypass_Board: C99 C100
component class "Components Class 1": C11 C12 C13 C14 C15 C16 C17 C18 C23 C24 C25 C26 C27 C28 C29 C30 C31 C32 C33 C34 C36 C37 C43 C44 C45 C46 C47 C48 C49 C50 C51 C52 C53 C54 C55 C56 C57 C58 C59 C60 C61 C62 C63 C64 C65 C66 C67 C68 C69 C70 C71 C72 C73 C74 C75 C76 C77 C78 C79 C80 C81 C82 C83 C84 C85 C86 C87 C88 C89 C90 C91 C92 C93 C94 C95 C96 C97 C98
polygon class deleteme: AGND-TOP "Bottom Layer-2V5" "Bottom Layer-GND" GROUND-BOTTOM-LAYER GROUND-MID1-LAYER GROUND-MID2-LAYER GROUND-MID3-LAYER GROUND-MID4-LAYER GROUND-TOP-LAYER MidLayer1-GND MidLayer2-GND MidLayer3-1V2 MidLayer3-GND MidLayer4-1V2 MidLayer4-GND "Top Layer-GND"

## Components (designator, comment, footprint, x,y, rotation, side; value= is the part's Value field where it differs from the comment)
"Altium Logo Bot1" "Altium" LOGO-ALTIUM 2177.16,129.92 r180 bottom
"Altium Logo Top1" "Altium" LOGO-ALTIUM 1051.18,129.92 r0 top
C1 "0.1uF 16V" CAPC1005-STAR 2807.08,3015.74 r180 bottom
C2 "10nF 16V" CAPC1005-STAR 2807.08,2968.5 r0 bottom
C3 "10uF 20V" CAPC3528-STAR 2156.88,1779.51 r270 bottom (schematic designator C42_FP)
C4 "10uF 20V" CAPC3528-STAR 2156.9,1157.57 r270 bottom (schematic designator C43_FP)
C5 "10uF 20V" CAPC3528-STAR 1838.56,2105.71 r0 bottom (schematic designator C103_FP)
C6 "10uF 20V" CAPC3528-STAR 1216.62,2105.72 r0 bottom (schematic designator C45_FP)
C7 "10uF 20V" CAPC3528-STAR 1830.68,839.26 r0 bottom (schematic designator C104_FP)
C8 "10uF 20V" CAPC3528-STAR 890.44,1165.44 r270 bottom (schematic designator C1_FP)
C9 "10uF 20V" CAPC3528-STAR 1208.75,839.26 r0 bottom (schematic designator C2_FP)
C10 "10uF 20V" CAPC3528-STAR 890.44,1787.37 r270 bottom (schematic designator C3_FP)
C11 "0.1uF 16V" CAPC1005-STAR 1596.05,1475.02 r0 bottom (schematic designator C5_FP)
C12 "0.1uF 16V" CAPC1005-STAR 1610.24,1399.61 r0 bottom (schematic designator C8_FP)
C13 "0.1uF 16V" CAPC1005-STAR 1524.22,1441.56 r270 bottom (schematic designator C9_FP)
C14 "0.1uF 16V" CAPC1005-STAR 1074.53,1952.26 r180 bottom (schematic designator C11_FP)
C15 "10nF 16V" CAPC1005-STAR 1522.64,1529.53 r90 bottom (schematic designator C13_FP)
C16 "10nF 16V" CAPC1005-STAR 1524.22,1361.86 r270 bottom (schematic designator C15_FP)
C17 "10nF 16V" CAPC1005-STAR 1429.13,1479.33 r180 bottom (schematic designator C16_FP)
C18 "10nF 16V" CAPC1005-STAR 1641.73,1570.87 r90 bottom (schematic designator C18_FP)
C19 "10uF 20V" CAPC3528-STAR 2090.68,899.91 r225 bottom (schematic designator C44_FP)
C20 "10uF 20V" CAPC3528-STAR 951,905.48 r315 bottom (schematic designator C102_FP)
C21 "10uF 20V" CAPC3528-STAR 2096.25,2039.42 r315 bottom (schematic designator C20_FP)
C22 "10uF 20V" CAPC3528-STAR 956.57,2044.99 r225 bottom (schematic designator C21_FP)
C23 "0.1uF 16V" CAPC1005-STAR 1759.39,1475.02 r0 bottom (schematic designator C22_FP)
C24 "0.1uF 16V" CAPC1005-STAR 1720.47,1690.94 r90 bottom (schematic designator C23_FP)
C25 "0.1uF 16V" CAPC1005-STAR 1122.05,1120.08 r180 bottom (schematic designator C24_FP)
C26 "0.1uF 16V" CAPC1005-STAR 1604.33,1846.46 r90 bottom (schematic designator C25_FP)
C27 "0.1uF 16V" CAPC1005-STAR 1525.59,1273.62 r270 bottom (schematic designator C26_FP)
C28 "10nF 16V" CAPC1005-STAR 1934.54,1394.33 r0 bottom (schematic designator C27_FP)
C29 "10nF 16V" CAPC1005-STAR 1677.72,1475.02 r180 bottom (schematic designator C28_FP)
C30 "10nF 16V" CAPC1005-STAR 1329.72,1478.35 r180 bottom (schematic designator C29_FP)
C31 "10nF 16V" CAPC1005-STAR 1995.55,1991.62 r315 bottom (schematic designator C30_FP)
C32 "10nF 16V" CAPC1005-STAR 1147.34,951.53 r0 bottom (schematic designator C31_FP)
C33 "10nF 16V" CAPC1005-STAR 1677.17,1106.3 r270 bottom (schematic designator C32_FP)
C34 "10nF 16V" CAPC1005-STAR 1953.74,1688.98 r270 bottom (schematic designator C33_FP)
C35 "10nF 16V" CAPC1005-STAR 997.78,1008.6 r315 bottom (schematic designator C34_FP)
C36 "10nF 16V" CAPC1005-STAR 2036.88,1740.7 r90 bottom (schematic designator C35_FP)
C37 "10nF 16V" CAPC1005-STAR 1521.26,1611.79 r270 bottom (schematic designator C36_FP)
C38 "10nF 16V" CAPC1005-STAR 2029.01,1286.09 r90 bottom (schematic designator C37_FP)
C39 "10uF 20V" CAPC3528-STAR 1519.73,839.26 r0 bottom (schematic designator C38_FP)
C40 "10uF 20V" CAPC3528-STAR 2156.9,1468.56 r270 bottom (schematic designator C39_FP)
C41 "10uF 20V" CAPC3528-STAR 1527.59,2105.71 r0 bottom locked (schematic designator C40_FP)
C42 "10uF 20V" CAPC3528-STAR 890.44,1476.43 r270 bottom (schematic designator C41_FP)
C43 "0.1uF 16V" CAPC1005-STAR 1932.58,1476 r0 bottom (schematic designator C72_FP)
C44 "0.1uF 16V" CAPC1005-STAR 1128.94,1477.36 r180 bottom (schematic designator C75_FP)
C45 "0.1uF 16V" CAPC1005-STAR 1495.08,1679.13 r0 bottom (schematic designator C76_FP)
C46 "0.1uF 16V" CAPC1005-STAR 1221.46,1477.36 r0 bottom (schematic designator C77_FP)
C47 "0.1uF 16V" CAPC1005-STAR 1459.27,989.9 r270 bottom (schematic designator C78_FP)
C48 "0.1uF 16V" CAPC1005-STAR 1322.5,1659.02 r90 bottom (schematic designator C86_FP)
C49 "0.1uF 16V" CAPC1005-STAR 1405.51,1287.01 r90 bottom (schematic designator C90_FP)
C50 "0.1uF 16V" CAPC1005-STAR 1843.5,1476.38 r180 bottom (schematic designator C92_FP)
C51 "0.1uF 16V" CAPC1005-STAR 1525.59,1762.8 r270 bottom (schematic designator C93_FP)
C52 "0.1uF 16V" CAPC1005-STAR 1521.65,1068.9 r270 bottom (schematic designator C83_FP)
C53 "0.1uF 16V" CAPC1005-STAR 1523.62,1168.31 r90 bottom (schematic designator C82_FP)
C54 "0.1uF 16V" CAPC1005-STAR 1795.28,1133.86 r90 bottom (schematic designator C46_FP)
C55 "0.1uF 16V" CAPC1005-STAR 1890.75,1006.89 r0 bottom (schematic designator C47_FP)
C56 "0.1uF 16V" CAPC1005-STAR 1721.46,1815.94 r90 bottom (schematic designator C48_FP)
C57 "0.1uF 16V" CAPC1005-STAR 1033.46,1320.87 r180 bottom (schematic designator C49_FP)
C58 "0.1uF 16V" CAPC1005-STAR 2034.91,1653.12 r270 bottom (schematic designator C50_FP)
C59 "0.1uF 16V" CAPC1005-STAR 1117.82,1282.15 r180 bottom (schematic designator C51_FP)
C60 "0.1uF 16V" CAPC1005-STAR 1036.15,1171.94 r90 bottom (schematic designator C52_FP)
C61 "0.1uF 16V" CAPC1005-STAR 1566.53,989.9 r270 bottom (schematic designator C53_FP)
C62 "0.1uF 16V" CAPC1005-STAR 1025.59,1557.09 r180 bottom (schematic designator C54_FP)
C63 "0.1uF 16V" CAPC1005-STAR 1142.42,1962.1 r90 bottom (schematic designator C55_FP)
C64 "0.1uF 16V" CAPC1005-STAR 1878.94,1992.13 r90 bottom (schematic designator C56_FP)
C65 "0.1uF 16V" CAPC1005-STAR 1005.65,1900.1 r90 bottom (schematic designator C57_FP)
C66 "0.1uF 16V" CAPC1005-STAR 1247.64,987.2 r180 bottom (schematic designator C58_FP)
C67 "0.1uF 16V" CAPC1005-STAR 2035.43,1569.88 r270 bottom (schematic designator C59_FP)
C68 "0.1uF 16V" CAPC1005-STAR 1019.42,1697.4 r90 bottom (schematic designator C60_FP)
C69 "0.1uF 16V" CAPC1005-STAR 1036.15,1392.36 r180 bottom (schematic designator C61_FP)
C70 "10nF 16V" CAPC1005-STAR 1600.39,1657.48 r270 bottom (schematic designator C62_FP)
C71 "10nF 16V" CAPC1005-STAR 1334.65,1354.33 r0 bottom (schematic designator C63_FP)
C72 "10nF 16V" CAPC1005-STAR 1026.31,1618.68 r180 bottom (schematic designator C64_FP)
C73 "10nF 16V" CAPC1005-STAR 1098.14,1210.32 r90 bottom (schematic designator C65_FP)
C74 "10nF 16V" CAPC1005-STAR 2055.58,1930.61 r135 bottom (schematic designator C66_FP)
C75 "10nF 16V" CAPC1005-STAR 1959.65,1569.88 r270 bottom (schematic designator C67_FP)
C76 "10nF 16V" CAPC1005-STAR 1703.74,1357.28 r180 bottom (schematic designator C68_FP)
C77 "10nF 16V" CAPC1005-STAR 1343.5,1591.54 r0 bottom (schematic designator C69_FP)
C78 "10nF 16V" CAPC1005-STAR 1406.5,1736.22 r90 bottom (schematic designator C70_FP)
C79 "10nF 16V" CAPC1005-STAR 1526.57,1842.52 r90 bottom (schematic designator C71_FP)
C80 "10nF 16V" CAPC1005-STAR 1648.2,988.92 r270 bottom (schematic designator C73_FP)
C81 "10nF 16V" CAPC1005-STAR 1725.94,1994.57 r90 bottom (schematic designator C74_FP)
C82 "10nF 16V" CAPC1005-STAR 1511.42,990.89 r270 bottom (schematic designator C79_FP)
C83 "10nF 16V" CAPC1005-STAR 1040.09,1072.56 r0 bottom (schematic designator C80_FP)
C84 "10nF 16V" CAPC1005-STAR 1165.06,1004.66 r0 bottom (schematic designator C81_FP)
C85 "10nF 16V" CAPC1005-STAR 1025.33,1783.01 r270 bottom (schematic designator C100_FP)
C86 "10nF 16V" CAPC1005-STAR 1786.42,982.28 r270 bottom (schematic designator C84_FP)
C87 "10nF 16V" CAPC1005-STAR 2035.9,1834.18 r270 bottom (schematic designator C85_FP)
C88 "10nF 16V" CAPC1005-STAR 2028.02,1373.66 r90 bottom (schematic designator C101_FP)
C89 "10nF 16V" CAPC1005-STAR 2035.43,1144.68 r90 bottom (schematic designator C87_FP)
C90 "10nF 16V" CAPC1005-STAR 1374.65,974.16 r270 bottom (schematic designator C88_FP)
C91 "10nF 16V" CAPC1005-STAR 1318.56,972.19 r270 bottom (schematic designator C89_FP)
C92 "10nF 16V" CAPC1005-STAR 1081.42,1005.65 r180 bottom (schematic designator C91_FP)
C93 "10nF 16V" CAPC1005-STAR 2032.94,1052.88 r270 bottom (schematic designator C99_FP)
C94 "10nF 16V" CAPC1005-STAR 1111.92,1709.21 r180 bottom (schematic designator C98_FP)
C95 "10nF 16V" CAPC1005-STAR 1728.89,982.03 r270 bottom (schematic designator C94_FP)
C96 "10nF 16V" CAPC1005-STAR 1670.83,1994.57 r90 bottom (schematic designator C95_FP)
C97 "10nF 16V" CAPC1005-STAR 1379.92,1961.61 r90 bottom (schematic designator C96_FP)
C98 "10nF 16V" CAPC1005-STAR 1023.36,1263.46 r180 bottom (schematic designator C97_FP)
C99 "220uF 10V" CAPC7343-STAR 2814.96,2149.6 r180 top (schematic designator C1_MB)
C100 "220uF 10V" CAPC7343-STAR 1870.07,2862.2 r180 bottom (schematic designator C2_MB)
C101 "0.1uF 16V" CAPC1005-STAR 1259.84,236.22 r0 bottom (schematic designator C1_SL)
C102 "0.1uF 16V" CAPC1005-STAR 2370.07,2799.21 r180 bottom (schematic designator C1)
C103 "0.1uF 16V" CAPC1005-STAR 2263.78,3233.28 r180 bottom (schematic designator C2)
C104 "10nF 16V" CAPC1005-STAR 2185.04,2969.49 r270 bottom (schematic designator C3)
C105 "10nF 16V" CAPC1005-STAR 2370.07,2842.52 r180 bottom (schematic designator C4)
C106 "10nF 16V" CAPC1005-STAR 2263.78,3186.02 r180 bottom (schematic designator C5)
C107 "0.1uF 16V" CAPC1005-STAR 2141.73,2969.49 r270 bottom (schematic designator C6)
C108 "10uF 10V" CAPC2012-STAR 2765.76,3087.59 r0 bottom (schematic designator C23_CM)
C109 "10uF 10V" CAPC2012-STAR 2216.53,3986.21 r270 bottom (schematic designator C24_CM)
C110 "470pF 50V" CAPC1005-STAR 2944.88,1740.15 r90 top (schematic designator C2_PS)
C111 "2.2uF 10V" CAPC1608-STAR 2456.69,1692.91 r180 top (schematic designator C4_PS)
C112 "220uF 10V" CAPC7343-STAR 2492.13,1551.18 r0 bottom (schematic designator C3_PS)
C113 "10uF 10V" CAPC2012-STAR 2988.18,1425.19 r270 top (schematic designator C5_PS)
C114 "22uF 10V" CAPC3225-STAR 2748.03,1503.93 r180 top (schematic designator C6_PS)
C115 "10uF 10V" CAPC2012-STAR 3118.1,1795.27 r270 top (schematic designator C8_PS)
C116 "22uF 10V" CAPC3225-STAR 2637.79,1976.37 r180 top (schematic designator C1_PS)
C117 "1uF 25V" CAPC3216-STAR 2448.81,1783.46 r0 top (schematic designator C7_PS)
C118 "2.2uF 10V" CAPC1608-STAR 1744.09,2401.57 r180 top (schematic designator C3_LD)
C119 "2.2uF 10V" CAPC1608-STAR 1657.48,2515.74 r270 top (schematic designator C1_LD)
C120 "0.033uF 10V" CAPC1005-STAR 2015.74,2547.24 r0 top (schematic designator C2_LD)
C121 "0.1uF 16V" CAPC1005-STAR 2149.6,4007.87 r270 top (schematic designator C1)
C122 "0.1uF 16V" CAPC1005-STAR 1535.43,3374.01 r180 top (schematic designator C2)
C123 "0.1uF 16V" CAPC1005-STAR 1279.52,3405.5 r180 bottom (schematic designator C3)
C124 "0.1uF 16V" CAPC1005-STAR 1803.15,3999.99 r90 bottom (schematic designator C4)
C125 "10nF 16V" CAPC1005-STAR 1440.94,3980.31 r180 top (schematic designator C5)
C126 "10nF 16V" CAPC1005-STAR 1629.92,3980.31 r180 top (schematic designator C6)
C127 "10nF 16V" CAPC1005-STAR 2039.37,3374.01 r180 bottom (schematic designator C7)
C128 "10nF 16V" CAPC1005-STAR 1850.39,3374.01 r180 bottom (schematic designator C8)
C129 "0.1uF 16V" CAPC1005-STAR 2915.44,1059.04 r90 top (schematic designator C1_SM)
C130 "0.1uF 16V" CAPC1005-STAR 2306.5,1058.78 r270 top (schematic designator C2_SM)
C131 "10nF 16V" CAPC1005-STAR 2915.44,980.31 r270 top (schematic designator C3_SM)
C132 "10nF 16V" CAPC1005-STAR 2306.5,1058.78 r270 bottom (schematic designator C4_SM)
C133 "0.1uF 16V" CAPC1005-STAR 2391.82,980.31 r270 bottom (schematic designator C1_SM)
C134 "0.1uF 16V" CAPC1005-STAR 3007.87,1133.85 r90 bottom (schematic designator C2_SM)
C135 "10nF 16V" CAPC1005-STAR 2391.82,1062.98 r90 bottom (schematic designator C3_SM)
C136 "10nF 16V" CAPC1005-STAR 3007.87,1055.11 r270 bottom (schematic designator C4_SM)
C137 "0.1uF 16V" CAPC1005-STAR 2604.05,3326.76 r0 top (schematic designator C1)
C138 "0.1uF 16V" CAPC1005-STAR 2602.36,4027.55 r180 top (schematic designator C2)
C139 "0.1uF 16V" CAPC1005-STAR 2602.36,3330.7 r0 bottom (schematic designator C3)
C140 "0.1uF 16V" CAPC1005-STAR 2665.35,4027.56 r0 bottom (schematic designator C4)
C141 "10nF 16V" CAPC1005-STAR 2604.05,3370.07 r0 top (schematic designator C5)
C142 "10nF 16V" CAPC1005-STAR 2602.09,3984.24 r180 top (schematic designator C6)
C143 "10nF 16V" CAPC1005-STAR 2602.36,3370.07 r0 bottom (schematic designator C7)
C144 "10nF 16V" CAPC1005-STAR 2665.35,3984.24 r0 bottom (schematic designator C8)
HDR_B1 "MOLEX - 54075-1009" 54075 1893.7,472.44 r0 bottom locked (schematic designator HDR_B)
HDR_L1 "MOLEX - 54075-1009" 54075 307.09,1472.44 r270 bottom locked (schematic designator HDR_L)
HDR_T1 "MOLEX - 54075-1009" 54075 1893.7,2472.44 r0 bottom locked (schematic designator HDR_T)
L1 "2u2, 15A, 4R2, SMD" IND-EPCOS-SMD-B82559 2944.88,1649.6 r90 bottom (schematic designator L1_PS)
LED1 "GREEN" LED2012-STAR 1261.81,169.29 r180 top (schematic designator LED2_SL)
LED2 "RED" LED2012-STAR 1974.41,169.29 r180 top (schematic designator LED1_SL)
MH1 "MOUNTING HOLE 3MM" MOUNTING_HOLE_3MM 1618.11,129.92 r180 top locked
MH2 "MOUNTING HOLE 3MM" MOUNTING_HOLE_3MM 129.92,4326.77 r180 top locked
MH3 "MOUNTING HOLE 3MM" MOUNTING_HOLE_3MM 3106.3,4326.77 r180 top locked
NT1 "Net Tie SMT2" NETTIE-SMT2-8X8#1 1626.22,2700.43 r90 bottom net-tie
NT2 "Net Tie SMT2" NETTIE-SMT2-8X8#1 1752.2,2680.73 r90 bottom net-tie
NT3 "Net Tie SMT2" NETTIE-SMT2-8X8#1 1720.7,2680.73 r90 bottom net-tie
NT4 "Net Tie SMT2" NETTIE-SMT2-8X8#1 1689.21,2680.74 r90 bottom net-tie
NT5 "Net Tie SMT2" NETTIE-SMT2-8X8#1 1657.71,2680.74 r90 bottom net-tie
NT6 "Net Tie SMT2" NETTIE-SMT2-8X8#1 1464.21,258.23 r0 bottom net-tie
NT7 "Net Tie SMT2" NETTIE-SMT2-8X8#2 1523.23,1972.92 r0 top net-tie (schematic designator NT8)
NT8 "Net Tie SMT2" NETTIE-SMT2-8X8#1 2519.44,1982.83 r90 top net-tie (schematic designator NT7)
PBFREE "" LEAD_FREE_S 292.32,3631.89 r180 bottom
PCB1 "DB42 Blank PCB" "DB42 Blank PCB" 3232.27,98.42 r90 top
R1 "270R 1%" RESC1005-STAR 1248.03,169.29 r180 bottom (schematic designator R2_SL)
R2 "270R 1%" RESC1005-STAR 1974.41,169.29 r180 bottom (schematic designator R1_SL)
R3 "100R 1%" RESC1005-STAR 2262.05,2216.76 r180 bottom (schematic designator R8)
R4 "100R 1%" RESC1005-STAR 2360.8,2216.76 r180 bottom (schematic designator R9)
R5 "100R 1%" RESC1005-STAR 2261.98,2150.17 r180 bottom (schematic designator R10)
R6 "100R 1%" RESC1005-STAR 710.93,2187.32 r180 bottom (schematic designator R12)
R7 "100R 1%" RESC1005-STAR 710.93,2145.52 r180 bottom (schematic designator R24)
R8 "100R 1%" RESC1005-STAR 2346.46,1363.63 r0 bottom (schematic designator R22)
R9 "270R 1%" RESC1005-STAR 736.03,2790.62 r90 bottom (schematic designator R25)
R10 "4K7 1%" RESC1005-STAR 710.93,2103.73 r180 bottom (schematic designator R1)
R11 "4K7 1%" RESC1005-STAR 2360.74,2150.17 r0 bottom (schematic designator R2)
R12 "4K7 1%" RESC1005-STAR 2346.46,1317.04 r0 bottom (schematic designator R3)
R13 "4K7 1%" RESC1005-STAR 2346.46,1410.21 r0 bottom (schematic designator R4)
R14 "100R 1%" RESC1005-STAR 710.93,2020.14 r180 bottom
R15 "100R 1%" RESC1005-STAR 710.93,1978.35 r180 bottom (schematic designator R18)
R16 "100R 1%" RESC1005-STAR 710.93,2061.94 r180 bottom (schematic designator R23)
R17 "100R 1%" RESC1005-STAR 2346.46,1270.45 r0 bottom (schematic designator R20)
R18 "100K 1%" RESC1005-STAR 1826.77,2358.26 r180 top (schematic designator R1T)
R19 "10R 1%" RESC1005-STAR 2492.12,1622.04 r90 top (schematic designator R2_PS)
R20 "2K7 1%" RESC1005-STAR 2787.4,1866.14 r0 top (schematic designator R1_PS)
R21 "27K 1%" RESC1005-STAR 2889.76,1866.14 r0 top (schematic designator R3_PS)
R22 "2K7 1%" RESC1005-STAR 2992.12,1866.14 r0 top (schematic designator R4_PS)
R23 "100K 1%" RESC1005-STAR 2992.12,1814.96 r0 top (schematic designator R5_PS)
R24 "100K 1%" RESC1005-STAR 1720.47,2637.79 r0 top (schematic designator R1_LD)
R25 "100K 1%" RESC1005-STAR 1854.33,2413.38 r180 top (schematic designator R2_LD)
RN1 "RESNET 4 x 100R" RESNET-1005X4 1662.98,3301.18 r90 bottom (schematic designator RN33)
RN2 "RESNET 4 x 100R" RESNET-1005X4 1366.74,3301.18 r90 bottom (schematic designator RN35)
RN3 "RESNET 4 x 100R" RESNET-1005X4 1559.65,4025.59 r90 bottom (schematic designator RN37)
RN4 "RESNET 4 x 100R" RESNET-1005X4 1804.73,3301.18 r270 bottom (schematic designator RN34)
RN5 "RESNET 4 x 100R" RESNET-1005X4 1701.39,4025.59 r270 bottom (schematic designator RN38)
RN6 "RESNET 4 x 100R" RESNET-1005X4 1508.47,3301.18 r270 bottom (schematic designator RN36)
TP1 "GND" TESTPIN 2875.71,3138.67 r0 top (schematic designator TP0)
TP2 "3V3" TESTPIN 2875.71,3038.67 r0 top (schematic designator TP1)
TP3 "2V5" TESTPIN 2875.71,2938.67 r0 top (schematic designator TP2)
TP4 "5V0" TESTPIN 2875.71,2838.67 r0 top (schematic designator TP3)
TP5 "1V2" TESTPIN 2875.71,2738.67 r0 top (schematic designator TP4)
U1 "DS2406" TSOC6 2712.59,2846.45 r90 bottom
U2 "SN74LVC1G04DBV" SOT95P280-5 1397.63,165.35 r0 bottom (schematic designator U1_SL)
U3 "S29GL256N11FFIV10" BGA100P8X8-64 2370.08,3036.42 r180 top locked (schematic designator U1)
U4 "XC3SD1800A-4FG676C" BGA100P26X26-676 1523.62,1472.44 r0 top locked (schematic designator U1)
U5 "SN74LVC1G04DBV" SOT95P280-5 865.92,2799.48 r270 bottom (schematic designator U3)
U6 "MAX1831EEE" SOP63P602-16 2708.58,1720.75 r180 top locked (schematic designator U1_PS)
U7 "MAX8860EUA18+" SOP65P490-8 1826.77,2507.87 r0 top (schematic designator U11)
U8 "SDRAM-16Mx16" TSOP80P1176-54 1740.16,3677.16 r0 top locked (schematic designator U1)
U9 "SDRAM-16Mx16" TSOP80P1176-54 1740.16,3677.16 r180 bottom locked (schematic designator U2)
U10 "SRAM-256Kx16" TSOP80P1176-44 2612.3,1059.05 r90 top locked (schematic designator U1_SM)
U11 "SRAM-256Kx16" TSOP80P1176-44 2702.84,1059.04 r90 bottom locked (schematic designator U1_SM)
U12 "SRAM-256Kx16" TSOP80P1176-44 2602.36,3677.16 r0 top locked (schematic designator U1)
U13 "SRAM-256Kx16" TSOP80P1176-44 2665.35,3677.16 r180 bottom locked (schematic designator U2)

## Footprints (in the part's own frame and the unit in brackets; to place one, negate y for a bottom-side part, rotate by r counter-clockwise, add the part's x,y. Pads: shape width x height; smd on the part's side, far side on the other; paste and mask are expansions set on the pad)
54075 [mm]
  rect 0.5x1.9 smd: 1(-19.6,3.4) 2(-19.6,-3.4) 3(-18.8,3.4) 4(-18.8,-3.4) 5(-18,3.4) 6(-18,-3.4) 7(-17.2,3.4) 8(-17.2,-3.4) 9(-16.4,3.4) 10(-16.4,-3.4) 11(-15.6,3.4) 12(-15.6,-3.4) 13(-14.8,3.4) 14(-14.8,-3.4) 15(-14,3.4) 16(-14,-3.4) 17(-13.2,3.4) 18(-13.2,-3.4) 19(-12.4,3.4) 20(-12.4,-3.4) 21(-11.6,3.4) 22(-11.6,-3.4) 23(-10.8,3.4) 24(-10.8,-3.4) 25(-10,3.4) 26(-10,-3.4) 27(-9.2,3.4) 28(-9.2,-3.4) 29(-8.4,3.4) 30(-8.4,-3.4) 31(-7.6,3.4) 32(-7.6,-3.4) 33(-6.8,3.4) 34(-6.8,-3.4) 35(-6,3.4) 36(-6,-3.4) 37(-5.2,3.4) 38(-5.2,-3.4) 39(-4.4,3.4) 40(-4.4,-3.4) 41(-3.6,3.4) 42(-3.6,-3.4) 43(-2.8,3.4) 44(-2.8,-3.4) 45(-2,3.4) 46(-2,-3.4) 47(-1.2,3.4) 48(-1.2,-3.4) 49(-0.4,3.4) 50(-0.4,-3.4) 51(0.4,3.4) 52(0.4,-3.4) 53(1.2,3.4) 54(1.2,-3.4) 55(2,3.4) 56(2,-3.4) 57(2.8,3.4) 58(2.8,-3.4) 59(3.6,3.4) 60(3.6,-3.4) 61(4.4,3.4) 62(4.4,-3.4) 63(5.2,3.4) 64(5.2,-3.4) 65(6,3.4) 66(6,-3.4) 67(6.8,3.4) 68(6.8,-3.4) 69(7.6,3.4) 70(7.6,-3.4) 71(8.4,3.4) 72(8.4,-3.4) 73(9.2,3.4) 74(9.2,-3.4) 75(10,3.4) 76(10,-3.4) 77(10.8,3.4) 78(10.8,-3.4) 79(11.6,3.4) 80(11.6,-3.4) 81(12.4,3.4) 82(12.4,-3.4) 83(13.2,3.4) 84(13.2,-3.4) 85(14,3.4) 86(14,-3.4) 87(14.8,3.4) 88(14.8,-3.4) 89(15.6,3.4) 90(15.6,-3.4) 91(16.4,3.4) 92(16.4,-3.4) 93(17.2,3.4) 94(17.2,-3.4) 95(18,3.4) 96(18,-3.4) 97(18.8,3.4) 98(18.8,-3.4) 99(19.6,3.4) 100(19.6,-3.4)
  round 1.6 hole 0.7: MH1(-26.7,4.2) MH2(-25.9,-4.2) MH3(26.7,4.2) MH4(25.9,-4.2)
  round 4.8 hole 5.1 unplated: MH5(-26.3,0) MH6(26.3,0)
  Top Layer keep-out region: -20.15,2.15 20.15,2.15 20.15,-2.15 -20.15,-2.15
  silkscreen extent -30.35,-4.4 30.35,5.02, body extent -30.36,-4.42 30.34,4.38, height 3.75
BGA100P8X8-64 [mm] "AMD 64-Ball Fortfied Ball grid Array (FBGA)"
  round 0.5 smd: A1(-3.5,-3.5) A2(-3.5,-2.5) A3(-3.5,-1.5) A4(-3.5,-0.5) A5(-3.5,0.5) A6(-3.5,1.5) A7(-3.5,2.5) A8(-3.5,3.5) B1(-2.5,-3.5) B2(-2.5,-2.5) B3(-2.5,-1.5) B4(-2.5,-0.5) B5(-2.5,0.5) B6(-2.5,1.5) B7(-2.5,2.5) B8(-2.5,3.5) C1(-1.5,-3.5) C2(-1.5,-2.5) C3(-1.5,-1.5) C4(-1.5,-0.5) C5(-1.5,0.5) C6(-1.5,1.5) C7(-1.5,2.5) C8(-1.5,3.5) D1(-0.5,-3.5) D2(-0.5,-2.5) D3(-0.5,-1.5) D4(-0.5,-0.5) D5(-0.5,0.5) D6(-0.5,1.5) D7(-0.5,2.5) D8(-0.5,3.5) E1(0.5,-3.5) E2(0.5,-2.5) E3(0.5,-1.5) E4(0.5,-0.5) E5(0.5,0.5) E6(0.5,1.5) E7(0.5,2.5) E8(0.5,3.5) F1(1.5,-3.5) F2(1.5,-2.5) F3(1.5,-1.5) F4(1.5,-0.5) F5(1.5,0.5) F6(1.5,1.5) F7(1.5,2.5) F8(1.5,3.5) G1(2.5,-3.5) G2(2.5,-2.5) G3(2.5,-1.5) G4(2.5,-0.5) G5(2.5,0.5) G6(2.5,1.5) G7(2.5,2.5) G8(2.5,3.5) H1(3.5,-3.5) H2(3.5,-2.5) H3(3.5,-1.5) H4(3.5,-0.5) H5(3.5,0.5) H6(3.5,1.5) H7(3.5,2.5) H8(3.5,3.5)
  silkscreen extent -6.5,-6.32 6.5,5.5, body extent -6.35,-5.4 6.41,5.36, height 1
BGA100P26X26-676 [mm]
  round 0.5 smd: A1(-12.5,12.5) A2(-11.5,12.5) A3(-10.5,12.5) A4(-9.5,12.5) A5(-8.5,12.5) A6(-7.5,12.5) A7(-6.5,12.5) A8(-5.5,12.5) A9(-4.5,12.5) A10(-3.5,12.5) A11(-2.5,12.5) A12(-1.5,12.5) A13(-0.5,12.5) A14(0.5,12.5) A15(1.5,12.5) A16(2.5,12.5) A17(3.5,12.5) A18(4.5,12.5) A19(5.5,12.5) A20(6.5,12.5) A21(7.5,12.5) A22(8.5,12.5) A23(9.5,12.5) A24(10.5,12.5) A25(11.5,12.5) A26(12.5,12.5) AA1(-12.5,-7.5) AA2(-11.5,-7.5) AA3(-10.5,-7.5) AA4(-9.5,-7.5) AA5(-8.5,-7.5) AA6(-7.5,-7.5) AA7(-6.5,-7.5) AA8(-5.5,-7.5) AA9(-4.5,-7.5) AA10(-3.5,-7.5) AA11(-2.5,-7.5) AA12(-1.5,-7.5) AA13(-0.5,-7.5) AA14(0.5,-7.5) AA15(1.5,-7.5) AA16(2.5,-7.5) AA17(3.5,-7.5) AA18(4.5,-7.5) AA19(5.5,-7.5) AA20(6.5,-7.5) AA21(7.5,-7.5) AA22(8.5,-7.5) AA23(9.5,-7.5) AA24(10.5,-7.5) AA25(11.5,-7.5) AA26(12.5,-7.5) AB1(-12.5,-8.5) AB2(-11.5,-8.5) AB3(-10.5,-8.5) AB4(-9.5,-8.5) AB5(-8.5,-8.5) AB6(-7.5,-8.5) AB7(-6.5,-8.5) AB8(-5.5,-8.5) AB9(-4.5,-8.5) AB10(-3.5,-8.5) AB11(-2.5,-8.5) AB12(-1.5,-8.5) AB13(-0.5,-8.5) AB14(0.5,-8.5) AB15(1.5,-8.5) AB16(2.5,-8.5) AB17(3.5,-8.5) AB18(4.5,-8.5) AB19(5.5,-8.5) AB20(6.5,-8.5) AB21(7.5,-8.5) AB22(8.5,-8.5) AB23(9.5,-8.5) AB24(10.5,-8.5) AB25(11.5,-8.5) AB26(12.5,-8.5) AC1(-12.5,-9.5) AC2(-11.5,-9.5) AC3(-10.5,-9.5) AC4(-9.5,-9.5) AC5(-8.5,-9.5) AC6(-7.5,-9.5) AC7(-6.5,-9.5) AC8(-5.5,-9.5) AC9(-4.5,-9.5) AC10(-3.5,-9.5) AC11(-2.5,-9.5) AC12(-1.5,-9.5) AC13(-0.5,-9.5) AC14(0.5,-9.5) AC15(1.5,-9.5) AC16(2.5,-9.5) AC17(3.5,-9.5) AC18(4.5,-9.5) AC19(5.5,-9.5) AC20(6.5,-9.5) AC21(7.5,-9.5) AC22(8.5,-9.5) AC23(9.5,-9.5) AC24(10.5,-9.5) AC25(11.5,-9.5) AC26(12.5,-9.5) AD1(-12.5,-10.5) AD2(-11.5,-10.5) AD3(-10.5,-10.5) AD4(-9.5,-10.5) AD5(-8.5,-10.5) AD6(-7.5,-10.5) AD7(-6.5,-10.5) AD8(-5.5,-10.5) AD9(-4.5,-10.5) AD10(-3.5,-10.5) AD11(-2.5,-10.5) AD12(-1.5,-10.5) AD13(-0.5,-10.5) AD14(0.5,-10.5) AD15(1.5,-10.5) AD16(2.5,-10.5) AD17(3.5,-10.5) AD18(4.5,-10.5) AD19(5.5,-10.5) AD20(6.5,-10.5) AD21(7.5,-10.5) AD22(8.5,-10.5) AD23(9.5,-10.5) AD24(10.5,-10.5) AD25(11.5,-10.5) AD26(12.5,-10.5) AE1(-12.5,-11.5) AE2(-11.5,-11.5) AE3(-10.5,-11.5) AE4(-9.5,-11.5) AE5(-8.5,-11.5) AE6(-7.5,-11.5) AE7(-6.5,-11.5) AE8(-5.5,-11.5) AE9(-4.5,-11.5) AE10(-3.5,-11.5) AE11(-2.5,-11.5) AE12(-1.5,-11.5) AE13(-0.5,-11.5) AE14(0.5,-11.5) AE15(1.5,-11.5) AE16(2.5,-11.5) AE17(3.5,-11.5) AE18(4.5,-11.5) AE19(5.5,-11.5) AE20(6.5,-11.5) AE21(7.5,-11.5) AE22(8.5,-11.5) AE23(9.5,-11.5) AE24(10.5,-11.5) AE25(11.5,-11.5) AE26(12.5,-11.5) AF1(-12.5,-12.5) AF2(-11.5,-12.5) AF3(-10.5,-12.5) AF4(-9.5,-12.5) AF5(-8.5,-12.5) AF6(-7.5,-12.5) AF7(-6.5,-12.5) AF8(-5.5,-12.5) AF9(-4.5,-12.5) AF10(-3.5,-12.5) AF11(-2.5,-12.5) AF12(-1.5,-12.5) AF13(-0.5,-12.5) AF14(0.5,-12.5) AF15(1.5,-12.5) AF16(2.5,-12.5) AF17(3.5,-12.5) AF18(4.5,-12.5) AF19(5.5,-12.5) AF20(6.5,-12.5) AF21(7.5,-12.5) AF22(8.5,-12.5) AF23(9.5,-12.5) AF24(10.5,-12.5) AF25(11.5,-12.5) AF26(12.5,-12.5) B1(-12.5,11.5) B2(-11.5,11.5) B3(-10.5,11.5) B4(-9.5,11.5) B5(-8.5,11.5) B6(-7.5,11.5) B7(-6.5,11.5) B8(-5.5,11.5) B9(-4.5,11.5) B10(-3.5,11.5) B11(-2.5,11.5) B12(-1.5,11.5) B13(-0.5,11.5) B14(0.5,11.5) B15(1.5,11.5) B16(2.5,11.5) B17(3.5,11.5) B18(4.5,11.5) B19(5.5,11.5) B20(6.5,11.5) B21(7.5,11.5) B22(8.5,11.5) B23(9.5,11.5) B24(10.5,11.5) B25(11.5,11.5) B26(12.5,11.5) C1(-12.5,10.5) C2(-11.5,10.5) C3(-10.5,10.5) C4(-9.5,10.5) C5(-8.5,10.5) C6(-7.5,10.5) C7(-6.5,10.5) C8(-5.5,10.5) C9(-4.5,10.5) C10(-3.5,10.5) C11(-2.5,10.5) C12(-1.5,10.5) C13(-0.5,10.5) C14(0.5,10.5) C15(1.5,10.5) C16(2.5,10.5) C17(3.5,10.5) C18(4.5,10.5) C19(5.5,10.5) C20(6.5,10.5) C21(7.5,10.5) C22(8.5,10.5) C23(9.5,10.5) C24(10.5,10.5) C25(11.5,10.5) C26(12.5,10.5) D1(-12.5,9.5) D2(-11.5,9.5) D3(-10.5,9.5) D4(-9.5,9.5) D5(-8.5,9.5) D6(-7.5,9.5) D7(-6.5,9.5) D8(-5.5,9.5) D9(-4.5,9.5) D10(-3.5,9.5) D11(-2.5,9.5) D12(-1.5,9.5) D13(-0.5,9.5) D14(0.5,9.5) D15(1.5,9.5) D16(2.5,9.5) D17(3.5,9.5) D18(4.5,9.5) D19(5.5,9.5) D20(6.5,9.5) D21(7.5,9.5) D22(8.5,9.5) D23(9.5,9.5) D24(10.5,9.5) D25(11.5,9.5) D26(12.5,9.5) E1(-12.5,8.5) E2(-11.5,8.5) E3(-10.5,8.5) E4(-9.5,8.5) E5(-8.5,8.5) E6(-7.5,8.5) E7(-6.5,8.5) E8(-5.5,8.5) E9(-4.5,8.5) E10(-3.5,8.5) E11(-2.5,8.5) E12(-1.5,8.5) E13(-0.5,8.5) E14(0.5,8.5) E15(1.5,8.5) E16(2.5,8.5) E17(3.5,8.5) E18(4.5,8.5) E19(5.5,8.5) E20(6.5,8.5) E21(7.5,8.5) E22(8.5,8.5) E23(9.5,8.5) E24(10.5,8.5) E25(11.5,8.5) E26(12.5,8.5) F1(-12.5,7.5) F2(-11.5,7.5) F3(-10.5,7.5) F4(-9.5,7.5) F5(-8.5,7.5) F6(-7.5,7.5) F7(-6.5,7.5) F8(-5.5,7.5) F9(-4.5,7.5) F10(-3.5,7.5) F11(-2.5,7.5) F12(-1.5,7.5) F13(-0.5,7.5) F14(0.5,7.5) F15(1.5,7.5) F16(2.5,7.5) F17(3.5,7.5) F18(4.5,7.5) F19(5.5,7.5) F20(6.5,7.5) F21(7.5,7.5) F22(8.5,7.5) F23(9.5,7.5) F24(10.5,7.5) F25(11.5,7.5) F26(12.5,7.5) G1(-12.5,6.5) G2(-11.5,6.5) G3(-10.5,6.5) G4(-9.5,6.5) G5(-8.5,6.5) G6(-7.5,6.5) G7(-6.5,6.5) G8(-5.5,6.5) G9(-4.5,6.5) G10(-3.5,6.5) G11(-2.5,6.5) G12(-1.5,6.5) G13(-0.5,6.5) G14(0.5,6.5) G15(1.5,6.5) G16(2.5,6.5) G17(3.5,6.5) G18(4.5,6.5) G19(5.5,6.5) G20(6.5,6.5) G21(7.5,6.5) G22(8.5,6.5) G23(9.5,6.5) G24(10.5,6.5) G25(11.5,6.5) G26(12.5,6.5) H1(-12.5,5.5) H2(-11.5,5.5) H3(-10.5,5.5) H4(-9.5,5.5) H5(-8.5,5.5) H6(-7.5,5.5) H7(-6.5,5.5) H8(-5.5,5.5) H9(-4.5,5.5) H10(-3.5,5.5) H11(-2.5,5.5) H12(-1.5,5.5) H13(-0.5,5.5) H14(0.5,5.5) H15(1.5,5.5) H16(2.5,5.5) H17(3.5,5.5) H18(4.5,5.5) H19(5.5,5.5) H20(6.5,5.5) H21(7.5,5.5) H22(8.5,5.5) H23(9.5,5.5) H24(10.5,5.5) H25(11.5,5.5) H26(12.5,5.5) J1(-12.5,4.5) J2(-11.5,4.5) J3(-10.5,4.5) J4(-9.5,4.5) J5(-8.5,4.5) J6(-7.5,4.5) J7(-6.5,4.5) J8(-5.5,4.5) J9(-4.5,4.5) J10(-3.5,4.5) J11(-2.5,4.5) J12(-1.5,4.5) J13(-0.5,4.5) J14(0.5,4.5) J15(1.5,4.5) J16(2.5,4.5) J17(3.5,4.5) J18(4.5,4.5) J19(5.5,4.5) J20(6.5,4.5) J21(7.5,4.5) J22(8.5,4.5) J23(9.5,4.5) J24(10.5,4.5) J25(11.5,4.5) J26(12.5,4.5) K1(-12.5,3.5) K2(-11.5,3.5) K3(-10.5,3.5) K4(-9.5,3.5) K5(-8.5,3.5) K6(-7.5,3.5) K7(-6.5,3.5) K8(-5.5,3.5) K9(-4.5,3.5) K10(-3.5,3.5) K11(-2.5,3.5) K12(-1.5,3.5) K13(-0.5,3.5) K14(0.5,3.5) K15(1.5,3.5) K16(2.5,3.5) K17(3.5,3.5) K18(4.5,3.5) K19(5.5,3.5) K20(6.5,3.5) K21(7.5,3.5) K22(8.5,3.5) K23(9.5,3.5) K24(10.5,3.5) K25(11.5,3.5) K26(12.5,3.5) L1(-12.5,2.5) L2(-11.5,2.5) L3(-10.5,2.5) L4(-9.5,2.5) L5(-8.5,2.5) L6(-7.5,2.5) L7(-6.5,2.5) L8(-5.5,2.5) L9(-4.5,2.5) L10(-3.5,2.5) L11(-2.5,2.5) L12(-1.5,2.5) L13(-0.5,2.5) L14(0.5,2.5) L15(1.5,2.5) L16(2.5,2.5) L17(3.5,2.5) L18(4.5,2.5) L19(5.5,2.5) L20(6.5,2.5) L21(7.5,2.5) L22(8.5,2.5) L23(9.5,2.5) L24(10.5,2.5) L25(11.5,2.5) L26(12.5,2.5) M1(-12.5,1.5) M2(-11.5,1.5) M3(-10.5,1.5) M4(-9.5,1.5) M5(-8.5,1.5) M6(-7.5,1.5) M7(-6.5,1.5) M8(-5.5,1.5) M9(-4.5,1.5) M10(-3.5,1.5) M11(-2.5,1.5) M12(-1.5,1.5) M13(-0.5,1.5) M14(0.5,1.5) M15(1.5,1.5) M16(2.5,1.5) M17(3.5,1.5) M18(4.5,1.5) M19(5.5,1.5) M20(6.5,1.5) M21(7.5,1.5) M22(8.5,1.5) M23(9.5,1.5) M24(10.5,1.5) M25(11.5,1.5) M26(12.5,1.5) N1(-12.5,0.5) N2(-11.5,0.5) N3(-10.5,0.5) N4(-9.5,0.5) N5(-8.5,0.5) N6(-7.5,0.5) N7(-6.5,0.5) N8(-5.5,0.5) N9(-4.5,0.5) N10(-3.5,0.5) N11(-2.5,0.5) N12(-1.5,0.5) N13(-0.5,0.5) N14(0.5,0.5) N15(1.5,0.5) N16(2.5,0.5) N17(3.5,0.5) N18(4.5,0.5) N19(5.5,0.5) N20(6.5,0.5) N21(7.5,0.5) N22(8.5,0.5) N23(9.5,0.5) N24(10.5,0.5) N25(11.5,0.5) N26(12.5,0.5) P1(-12.5,-0.5) P2(-11.5,-0.5) P3(-10.5,-0.5) P4(-9.5,-0.5) P5(-8.5,-0.5) P6(-7.5,-0.5) P7(-6.5,-0.5) P8(-5.5,-0.5) P9(-4.5,-0.5) P10(-3.5,-0.5) P11(-2.5,-0.5) P12(-1.5,-0.5) P13(-0.5,-0.5) P14(0.5,-0.5) P15(1.5,-0.5) P16(2.5,-0.5) P17(3.5,-0.5) P18(4.5,-0.5) P19(5.5,-0.5) P20(6.5,-0.5) P21(7.5,-0.5) P22(8.5,-0.5) P23(9.5,-0.5) P24(10.5,-0.5) P25(11.5,-0.5) P26(12.5,-0.5) R1(-12.5,-1.5) R2(-11.5,-1.5) R3(-10.5,-1.5) R4(-9.5,-1.5) R5(-8.5,-1.5) R6(-7.5,-1.5) R7(-6.5,-1.5) R8(-5.5,-1.5) R9(-4.5,-1.5) R10(-3.5,-1.5) R11(-2.5,-1.5) R12(-1.5,-1.5) R13(-0.5,-1.5) R14(0.5,-1.5) R15(1.5,-1.5) R16(2.5,-1.5) R17(3.5,-1.5) R18(4.5,-1.5) R19(5.5,-1.5) R20(6.5,-1.5) R21(7.5,-1.5) R22(8.5,-1.5) R23(9.5,-1.5) R24(10.5,-1.5) R25(11.5,-1.5) R26(12.5,-1.5) T1(-12.5,-2.5) T2(-11.5,-2.5) T3(-10.5,-2.5) T4(-9.5,-2.5) T5(-8.5,-2.5) T6(-7.5,-2.5) T7(-6.5,-2.5) T8(-5.5,-2.5) T9(-4.5,-2.5) T10(-3.5,-2.5) T11(-2.5,-2.5) T12(-1.5,-2.5) T13(-0.5,-2.5) T14(0.5,-2.5) T15(1.5,-2.5) T16(2.5,-2.5) T17(3.5,-2.5) T18(4.5,-2.5) T19(5.5,-2.5) T20(6.5,-2.5) T21(7.5,-2.5) T22(8.5,-2.5) T23(9.5,-2.5) T24(10.5,-2.5) T25(11.5,-2.5) T26(12.5,-2.5) U1(-12.5,-3.5) U2(-11.5,-3.5) U3(-10.5,-3.5) U4(-9.5,-3.5) U5(-8.5,-3.5) U6(-7.5,-3.5) U7(-6.5,-3.5) U8(-5.5,-3.5) U9(-4.5,-3.5) U10(-3.5,-3.5) U11(-2.5,-3.5) U12(-1.5,-3.5) U13(-0.5,-3.5) U14(0.5,-3.5) U15(1.5,-3.5) U16(2.5,-3.5) U17(3.5,-3.5) U18(4.5,-3.5) U19(5.5,-3.5) U20(6.5,-3.5) U21(7.5,-3.5) U22(8.5,-3.5) U23(9.5,-3.5) U24(10.5,-3.5) U25(11.5,-3.5) U26(12.5,-3.5) V1(-12.5,-4.5) V2(-11.5,-4.5) V3(-10.5,-4.5) V4(-9.5,-4.5) V5(-8.5,-4.5) V6(-7.5,-4.5) V7(-6.5,-4.5) V8(-5.5,-4.5) V9(-4.5,-4.5) V10(-3.5,-4.5) V11(-2.5,-4.5) V12(-1.5,-4.5) V13(-0.5,-4.5) V14(0.5,-4.5) V15(1.5,-4.5) V16(2.5,-4.5) V17(3.5,-4.5) V18(4.5,-4.5) V19(5.5,-4.5) V20(6.5,-4.5) V21(7.5,-4.5) V22(8.5,-4.5) V23(9.5,-4.5) V24(10.5,-4.5) V25(11.5,-4.5) V26(12.5,-4.5) W1(-12.5,-5.5) W2(-11.5,-5.5) W3(-10.5,-5.5) W4(-9.5,-5.5) W5(-8.5,-5.5) W6(-7.5,-5.5) W7(-6.5,-5.5) W8(-5.5,-5.5) W9(-4.5,-5.5) W10(-3.5,-5.5) W11(-2.5,-5.5) W12(-1.5,-5.5) W13(-0.5,-5.5) W14(0.5,-5.5) W15(1.5,-5.5) W16(2.5,-5.5) W17(3.5,-5.5) W18(4.5,-5.5) W19(5.5,-5.5) W20(6.5,-5.5) W21(7.5,-5.5) W22(8.5,-5.5) W23(9.5,-5.5) W24(10.5,-5.5) W25(11.5,-5.5) W26(12.5,-5.5) Y1(-12.5,-6.5) Y2(-11.5,-6.5) Y3(-10.5,-6.5) Y4(-9.5,-6.5) Y5(-8.5,-6.5) Y6(-7.5,-6.5) Y7(-6.5,-6.5) Y8(-5.5,-6.5) Y9(-4.5,-6.5) Y10(-3.5,-6.5) Y11(-2.5,-6.5) Y12(-1.5,-6.5) Y13(-0.5,-6.5) Y14(0.5,-6.5) Y15(1.5,-6.5) Y16(2.5,-6.5) Y17(3.5,-6.5) Y18(4.5,-6.5) Y19(5.5,-6.5) Y20(6.5,-6.5) Y21(7.5,-6.5) Y22(8.5,-6.5) Y23(9.5,-6.5) Y24(10.5,-6.5) Y25(11.5,-6.5) Y26(12.5,-6.5)
  round 1 on Mech7 paste-0.55 mask+1: FID1(-15,15) FID1(15,-15)
  round 1 smd: FID1(-15,15) FID1(15,-15)
  Top Layer keep-out circle w0.2: c-15,15 r1
  Top Layer keep-out circle w0.2: c15,-15 r1
  silkscreen extent -14.77,-13.5 13.5,13.5, body extent -13.55,-13.45 13.45,13.55, height 2.6
CAPC1005-STAR [mm] "Chip Capacitor 1005"
  rect 0.6x0.6 smd: 1(-0.525,0) 2(0.525,0)
  silkscreen extent -0.05,-0.38 0.05,0.38, body extent -0.57,-0.3 0.57,0.3, height 0.2
CAPC1608-STAR [mm] "Capacitor SMD 0603 (1608)"
  rect 0.9x0.8 smd: 1(-0.8,0) 2(0.8,0)
  silkscreen extent 0,-0.4 0,0.4, body extent -1.11,-0.41 1.1,0.39, height 0.8
CAPC2012-STAR [mm] "0805 Capacitor SMD - Startronics"
  rect 1x1.25 smd: 1(-1,0) 2(1,0)
  silkscreen extent -0.4,-1 0.4,1, body extent -0.98,-0.64 0.87,0.6, height 0.8
CAPC3216-STAR [mm] "Capacitor 1206 (3216) for Startronics"
  rect 1x1.6 smd: 1(-1.45,0) 2(1.45,0)
  silkscreen extent -0.62,-1.1 0.62,1.1, body extent -1.64,-0.89 1.63,0.86, height 0.9
CAPC3225-STAR [mm] "1210 Capacitor SMD - Startronics"
  rect 1x2.75 smd: 1(-1.5,0) 2(1.5,0)
  silkscreen extent -0.7,-1.5 0.7,1.5, body extent -1.94,-1.2 1.89,1.29, height 1.5
CAPC3528-STAR [mm] "Capacitor 3.5x2.8mm (B-Case)"
  rect 2x2.2 smd: 1(-1.6,0) 2(1.6,0)
  silkscreen extent -3,-1.7 3.05,1.7, body extent -1.79,-1.54 1.8,1.54, height 1
CAPC7343-STAR [mm] "Capcacitor SMD 7.3 x 4.3mm (D-Case)"
  rect 2.6x2.4 smd: 1(-3.202,0.007) 2(3.198,0.007)
  silkscreen extent -5.33,-2.39 5.08,2.41, body extent -3.49,-2.03 3.51,2.04, height 4.05
"DB42 Blank PCB" [mil]
IND-EPCOS-SMD-B82559 [mm]
  rect 4.4x10.4 smd: 1(0,0) 2(8.4,0)
  silkscreen extent -2.5,-5.5 11,5.5, body extent -2.54,-5.93 11,5.77, height 4.95
LEAD_FREE_S [mil]
  silkscreen extent -125,-125 125,125
LED2012-STAR [mm] "0805 LED SMD - Startronics"
  rect 1x1.25 smd: 1(1,0) 2(-1,0)
  silkscreen extent -2.27,-1 1.8,1, body extent -1.6,-0.6 1.5,0.6, height 0.67
LOGO-ALTIUM [mil]
  silkscreen extent -1025,-99 -556,102
MOUNTING_HOLE_3MM [mm] "Non-plated mounting hole for 3mm screw"
  round 3.8 hole 3.4: MOUNT(0,0)
  Top Layer circle w1: c0,0 r2.3
  Top Layer region: -2.8,-2.8 2.8,-2.8 2.8,2.8 -2.8,2.8
  Top Layer keep-out region: -3.3,-3.3 3.3,-3.3 3.3,3.3 -3.3,3.3
  Bottom Layer region: -2.8,-2.8 2.8,-2.8 2.8,2.8 -2.8,2.8
  Bottom Layer keep-out region: -3.3,-3.3 3.3,-3.3 3.3,3.3 -3.3,3.3
  Keep-Out Layer circle w1.2: c0,0 r2.5
NETTIE-SMT2-8X8#1 [mm]
  rect 0.4x0.2 smd paste+0: 1(-0.891,-0.006) 2(-0.691,-0.006)
NETTIE-SMT2-8X8#2 [mm]
  rect 0.4x0.2 on Mid3 paste+0 mask-1: 1(-0.891,-0.006) 2(-0.691,-0.006)
RESC1005-STAR [mm] "Chip Inductor 1005"
  rect 0.575x0.6 smd: 1(-0.538,0) 2(0.538,0)
  silkscreen extent -0.05,-0.38 0.05,0.38, body extent -0.71,-0.25 0.72,0.26, height 0.25
RESNET-1005X4 [mm] "Resistor network 4 x 1005 (0402)"
  rect 0.3x0.83 smd: 1(-0.75,-0.64) 2(-0.25,-0.64) 3(0.25,-0.64) 4(0.75,-0.64) 5(0.75,0.64) 6(0.25,0.64) 7(-0.25,0.64) 8(-0.75,0.64)
  silkscreen extent -1.15,-1 1.15,1, body extent -0.92,-0.84 1.04,0.81, height 0.4
SOP63P602-16 [mil]
  rect 82x16 smd: 1(-116,87.5) 2(-116,62) 3(-116,37.5) 4(-116,12.5) 5(-116,-12.5) 6(-116,-37.5) 7(-116,-62.5) 8(-116,-87.5) 9(116,-87.5) 10(116,-62.5) 11(116,-37.5) 12(116,-12.5) 13(116,12.5) 14(116,37.5) 15(116,62.5) 16(116,87.5)
  silkscreen extent -100,-100 60,125, body extent -107,-100 108,103, height 29
SOP65P490-8 [mm]
  rect 1.5x0.35 smd: 1(-2.275,0.975) 2(-2.3,0.325) 3(-2.3,-0.325) 4(-2.3,-0.975) 5(2.275,-0.975) 6(2.275,-0.325) 7(2.3,0.325) 8(2.3,0.975)
  silkscreen extent -2.38,-1.3 1.3,1.75, body extent -2.39,-1.23 2.41,1.28, height 1
SOT95P280-5 [mm] "SOT-23/SC-74A; 5 Leads; Body 3.1 x 3 mm, inc. leads (LxW max)"
  rect 0.6x1.3 smd: 1(-0.95,-1.4) 2(0,-1.4) 3(0.95,-1.4) 4(0.95,1.4)
  rect 0.6x1.25 smd: 5(-0.95,1.4)
  silkscreen extent -1.55,-0.9 1.55,0.9, body extent -1.51,-1.49 1.52,1.52, height 0.8
TESTPIN [mil]
  round 60 hole 35.43: 1(0,0)
  silkscreen extent -41,-39 156,39
TSOC6 [mil]
  rect 25x71 smd: 1(-50,-75) 2(0,-75) 3(50,-75) 4(50,75) 5(0,75) 6(-50,75)
  silkscreen extent -115,-80 85,80, body extent -79,-90 84,91, height 40
TSOP80P1176-44 [mm]
  rect 0.5x1.4 smd: 1(-8.4,-5.7) 2(-7.6,-5.7) 3(-6.8,-5.7) 4(-6,-5.7) 5(-5.2,-5.7) 6(-4.4,-5.7) 7(-3.6,-5.7) 8(-2.8,-5.7) 9(-2,-5.7) 10(-1.2,-5.7) 11(-0.4,-5.7) 12(0.4,-5.7) 13(1.2,-5.7) 14(2,-5.7) 15(2.8,-5.7) 16(3.6,-5.7) 17(4.4,-5.7) 18(5.2,-5.7) 19(6,-5.7) 20(6.8,-5.7) 21(7.6,-5.7) 22(8.4,-5.7) 23(8.4,5.7) 24(7.6,5.7) 25(6.8,5.7) 26(6,5.7) 27(5.2,5.7) 28(4.4,5.7) 29(3.6,5.7) 30(2.8,5.7) 31(2,5.7) 32(1.2,5.7) 33(0.4,5.7) 34(-0.4,5.7) 35(-1.2,5.7) 36(-2,5.7) 37(-2.8,5.7) 38(-3.6,5.7) 39(-4.4,5.7) 40(-5.2,5.7) 41(-6,5.7) 42(-6.8,5.7) 43(-7.6,5.7) 44(-8.4,5.7)
  silkscreen extent -9.29,-5.7 9.26,4.45, body extent -9.24,-5.95 9.26,5.84, height 1
TSOP80P1176-54 [mm] "Plastic Small Outline; 54 Leads; Body Width 10.16 mm"
  rect 0.5x1.4 smd: 1(-10.4,-5.7) 2(-9.6,-5.7) 3(-8.8,-5.7) 4(-8,-5.7) 5(-7.2,-5.7) 6(-6.4,-5.7) 7(-5.6,-5.7) 8(-4.8,-5.7) 9(-4,-5.7) 10(-3.2,-5.7) 11(-2.4,-5.7) 12(-1.6,-5.7) 13(-0.8,-5.7) 14(0,-5.7) 15(0.8,-5.7) 16(1.6,-5.7) 17(2.4,-5.7) 18(3.2,-5.7) 19(4,-5.7) 20(4.8,-5.7) 21(5.6,-5.7) 22(6.4,-5.7) 23(7.2,-5.7) 24(8,-5.7) 25(8.8,-5.7) 26(9.6,-5.7) 27(10.4,-5.7) 28(10.4,5.7) 29(9.6,5.7) 30(8.8,5.7) 31(8,5.7) 32(7.2,5.7) 33(6.4,5.7) 34(5.6,5.7) 35(4.8,5.7) 36(4,5.7) 37(3.2,5.7) 38(2.4,5.7) 39(1.6,5.7) 40(0.8,5.7) 41(0,5.7) 42(-0.8,5.7) 43(-1.6,5.7) 44(-2.4,5.7) 45(-3.2,5.7) 46(-4,5.7) 47(-4.8,5.7) 48(-5.6,5.7) 49(-6.4,5.7) 50(-7.2,5.7) 51(-8,5.7) 52(-8.8,5.7) 53(-9.6,5.7) 54(-10.4,5.7)
  silkscreen extent -11.33,-5.67 11.15,4.4, body extent -11.23,-5.96 11.19,5.97, height 1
